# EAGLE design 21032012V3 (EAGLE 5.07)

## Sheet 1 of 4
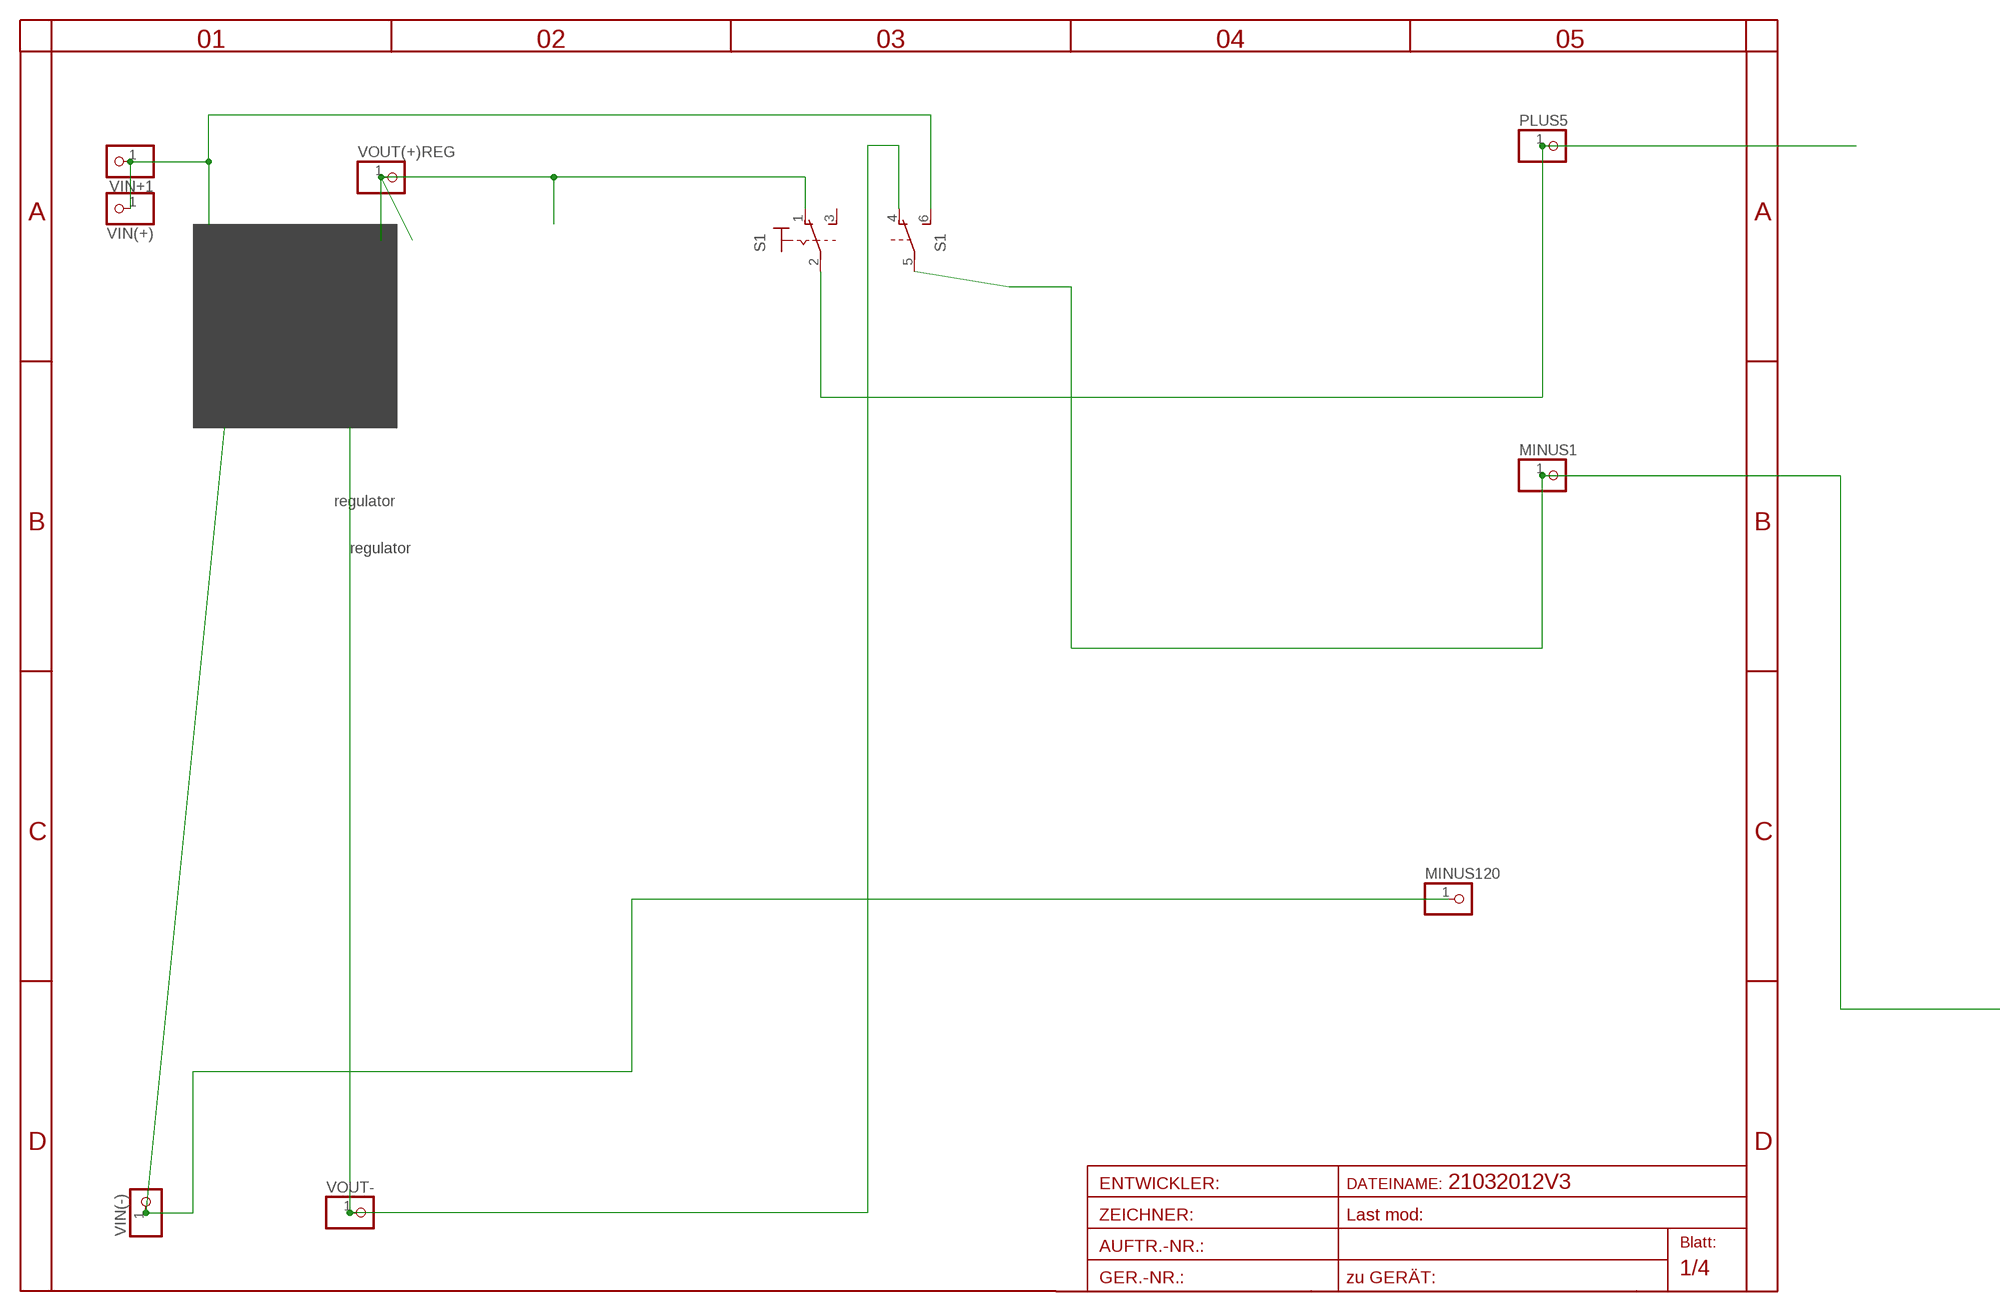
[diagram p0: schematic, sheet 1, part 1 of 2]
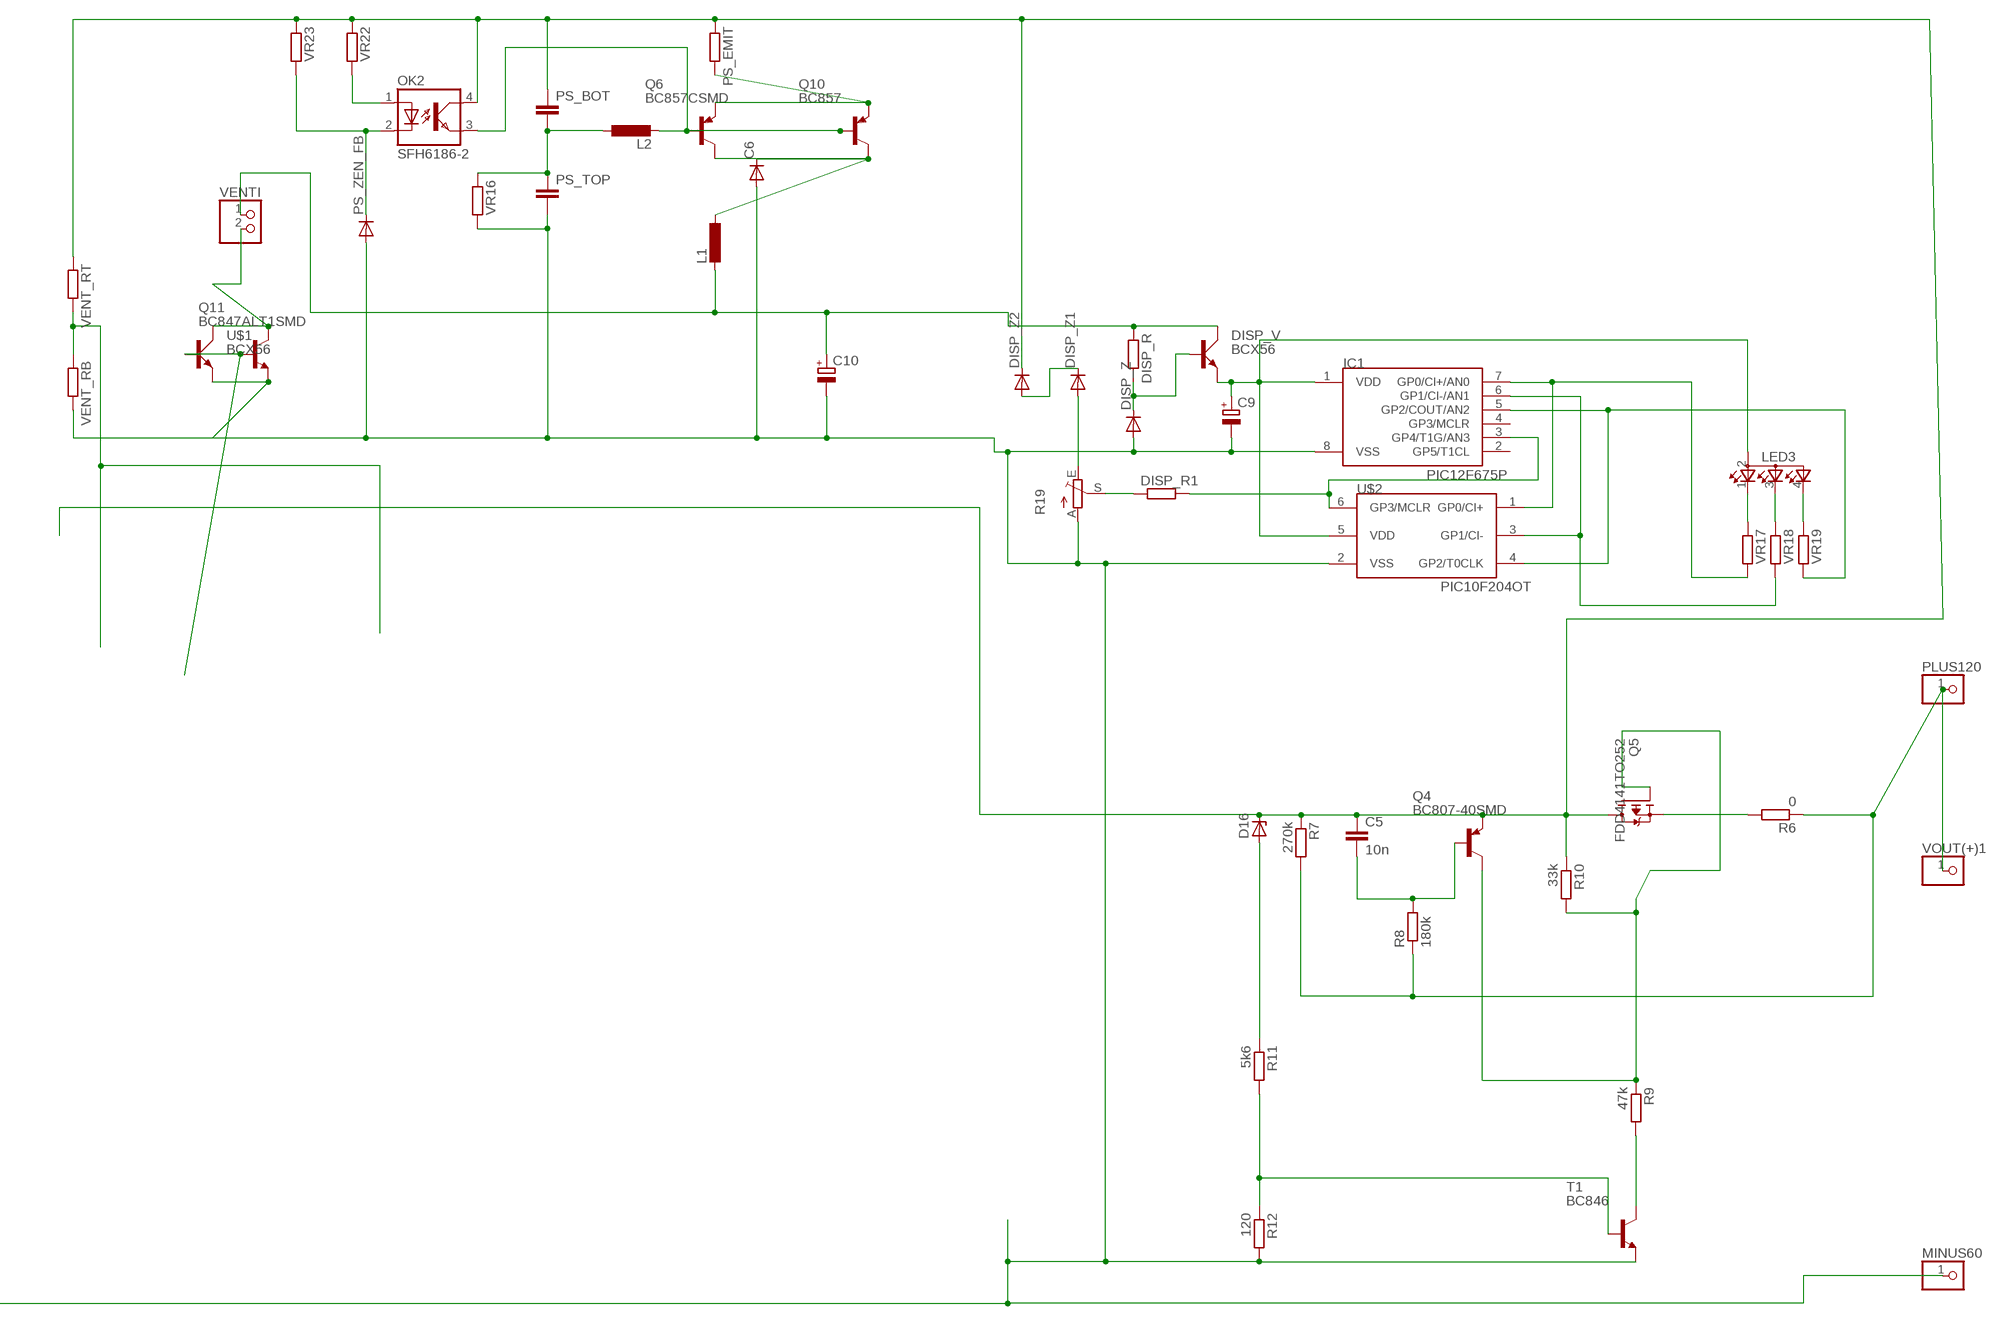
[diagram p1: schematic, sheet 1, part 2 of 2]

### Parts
C5  10n  C-EUC1206  [C1206]
C6  DIODE-SMB  [SMB]
C9  CPOL-EUE5-6  [E5-6]
C10  CPOL-EUE2.5-6  [E2,5-6]
D16  ZENER-DIODESOD80C  [SOD80C]
DISP_R  R-EU_R1206  [R1206]
DISP_R1  R-EU_R1206  [R1206]
DISP_V  BCX56  [SOT223]
DISP_Z  DIODE-MINIMELF  [MINIMELF]
DISP_Z1  DIODE-MINIMELF  [MINIMELF]
DISP_Z2  DIODE-MINIMELF  [MINIMELF]
IC1  PIC12F675P  [DIL8]
L1  L-EUL5650M  [L5650M]
L2  L-EUL5650M  [L5650M]
LED3  TOPLED-3  [P-LCC-4-3]
MINUS1  PINHD-1X14.5MM  [1X4MM5]
MINUS60  PINHD-1X14.5MM  [1X4MM5]
MINUS120  PINHD-1X14.5MM  [1X4MM5]
OK2  SFH6186-2  [SMD4]
PLUS5  PINHD-1X14.5MM  [1X4MM5]
PLUS120  PINHD-1X14.5MM  [1X4MM5]
PS_BOT  C-EUC1206  [C1206]
PS_EMIT  R-EU_R1210  [R1210]
PS_TOP  C-EUC1206  [C1206]
PS_ZEN_FB  DIODE-MINIMELF  [MINIMELF]
Q4  BC807-40SMD  [SOT23-BEC]
Q5  FDD4141TO252  [TO252]
Q6  BC857CSMD  [SOT23-BEC]
Q10  BC857  [SOT223]
Q11  BC847ALT1SMD  [SOT23]
R6  0  R-EU_0204/7  [0204/7]
R7  270k  R-EU_R1206  [R1206]
R8  180k  R-EU_R1206  [R1206]
R9  47k  R-EU_R1206  [R1206]
R10  33k  R-EU_R1206  [R1206]
R11  5k6  R-EU_R1206  [R1206]
R12  120  R-EU_R1206  [R1206]
R19  TRIM_EU-CA6V  [CA6V]
S1  320-938320NEW  [320NEW]
T1  BC846  [SOT23]
U$1  BCX56  [SOT223]
U$2  PIC10F204OT  [SOT23-6]
VENT_RB  R-EU_R1206  [R1206]
VENT_RT  R-EU_R1206  [R1206]
VENTI  PINHD-1X2  [1X02]
VIN(+)  PINHD-1X11MM6  [1X1MM8]
VIN(-)  PINHD-1X1  [1X01]
VIN+1  PINHD-1X1  [1X01]
VOUT(+)1  PINHD-1X11X0.4  [1X01]
VOUT(+)REG  PINHD-1X11X0.4  [1X01]
VOUT-  PINHD-1X11X0.4  [1X01]
VR16  R-EU_R1206  [R1206]
VR17  R-EU_R1206  [R1206]
VR18  R-EU_R1206  [R1206]
VR19  R-EU_R1206  [R1206]
VR22  R-EU_R1206  [R1206]
VR23  R-EU_R1206  [R1206]

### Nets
B-Q1: C5.2 Q4.B R8.2
BATT-: C6.A C9.- C10.- DISP_Z.A IC1.8(VSS) MINUS1.1 MINUS60.1 PS_TOP.2 PS_ZEN_FB.A Q11.2(E) R12.2 R19.A S1.5(B:P) T1.2(E) U$1.3(E) U$2.2(VSS) VENT_RB.2 VR16.2 ; also sheet 4
D: Q5.3(S) R6.2
GATE: Q4.C Q5.1(G) R9.1 R10.2
IN-: MINUS120.1 VIN(-).1 ; also sheet 3
N$18: R9.2 T1.3(C)
N$19: D16.A R11.1
N$21: R11.2 R12.1 T1.1(B)
N$22: C10.+ DISP_R.1 DISP_V.2(C) L1.2 VENTI.1
N$34: C9.+ DISP_V.3(E) IC1.1(VDD) LED3.2(A2) U$2.5(VDD)
N$35: IC1.7(GP0/CI+/AN0) U$2.1(GP0/CI+) VR17.2
N$36: IC1.6(GP1/CI-/AN1) U$2.3(GP1/CI-) VR18.2
N$37: IC1.5(GP2/COUT/AN2) U$2.4(GP2/T0CLK) VR19.2
N$38: PS_EMIT.2 Q6.E Q10.3(E)
N$39: L2.2 OK2.3(EMIT) Q6.B Q10.1(B)
N$40: C6.C L1.1 Q6.C Q10.2(C)
N$41: OK2.2(C) PS_ZEN_FB.C VR23.2
N$42: OK2.1(A) VR22.2
N$43: L2.1 PS_BOT.2 PS_TOP.1 VR16.1
N$44: VENT_RB.1 VENT_RT.2 ; also sheet 4
N$45: Q11.1(B) U$1.1(B) ; also sheet 4
N$46: DISP_R.2 DISP_V.1(B) DISP_Z.C
N$47: LED3.1(CRED) VR17.1
N$48: LED3.3(CBLUE) VR18.1
N$49: LED3.4(CGREEN) VR19.1
N$53: Q11.3(C) U$1.2(C) VENTI.2
N$69: DISP_Z1.A R19.E
N$75: DISP_R1.2 IC1.3(GP4/T1G/AN3) U$2.6(GP3/MCLR)
N$76: DISP_R1.1 R19.S
N$83: DISP_Z1.C DISP_Z2.A
PLUS5: C5.1 D16.C DISP_Z2.C OK2.4(COL) PLUS5.1 PS_BOT.1 PS_EMIT.1 Q4.E Q5.2(D) R7.1 R10.1 S1.2(1:P) VENT_RT.1 VR22.1 VR23.1 ; also sheet 4
V+OUT: PLUS120.1 R6.1 R7.2 R8.1 VOUT(+)1.1
V-: S1.4(B:O) VOUT-.1 ; also sheet 3
VIN+: S1.6(B:S) VIN(+).1 VIN+1.1 ; also sheet 3
VOUT+REG: S1.1(1:O) VOUT(+)REG.1 ; also sheet 2,3
Unconnected: IC1.2(GP5/T1CL) IC1.4(GP3/MCLR) S1.3(1:S)

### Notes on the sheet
- regulator
- regulator

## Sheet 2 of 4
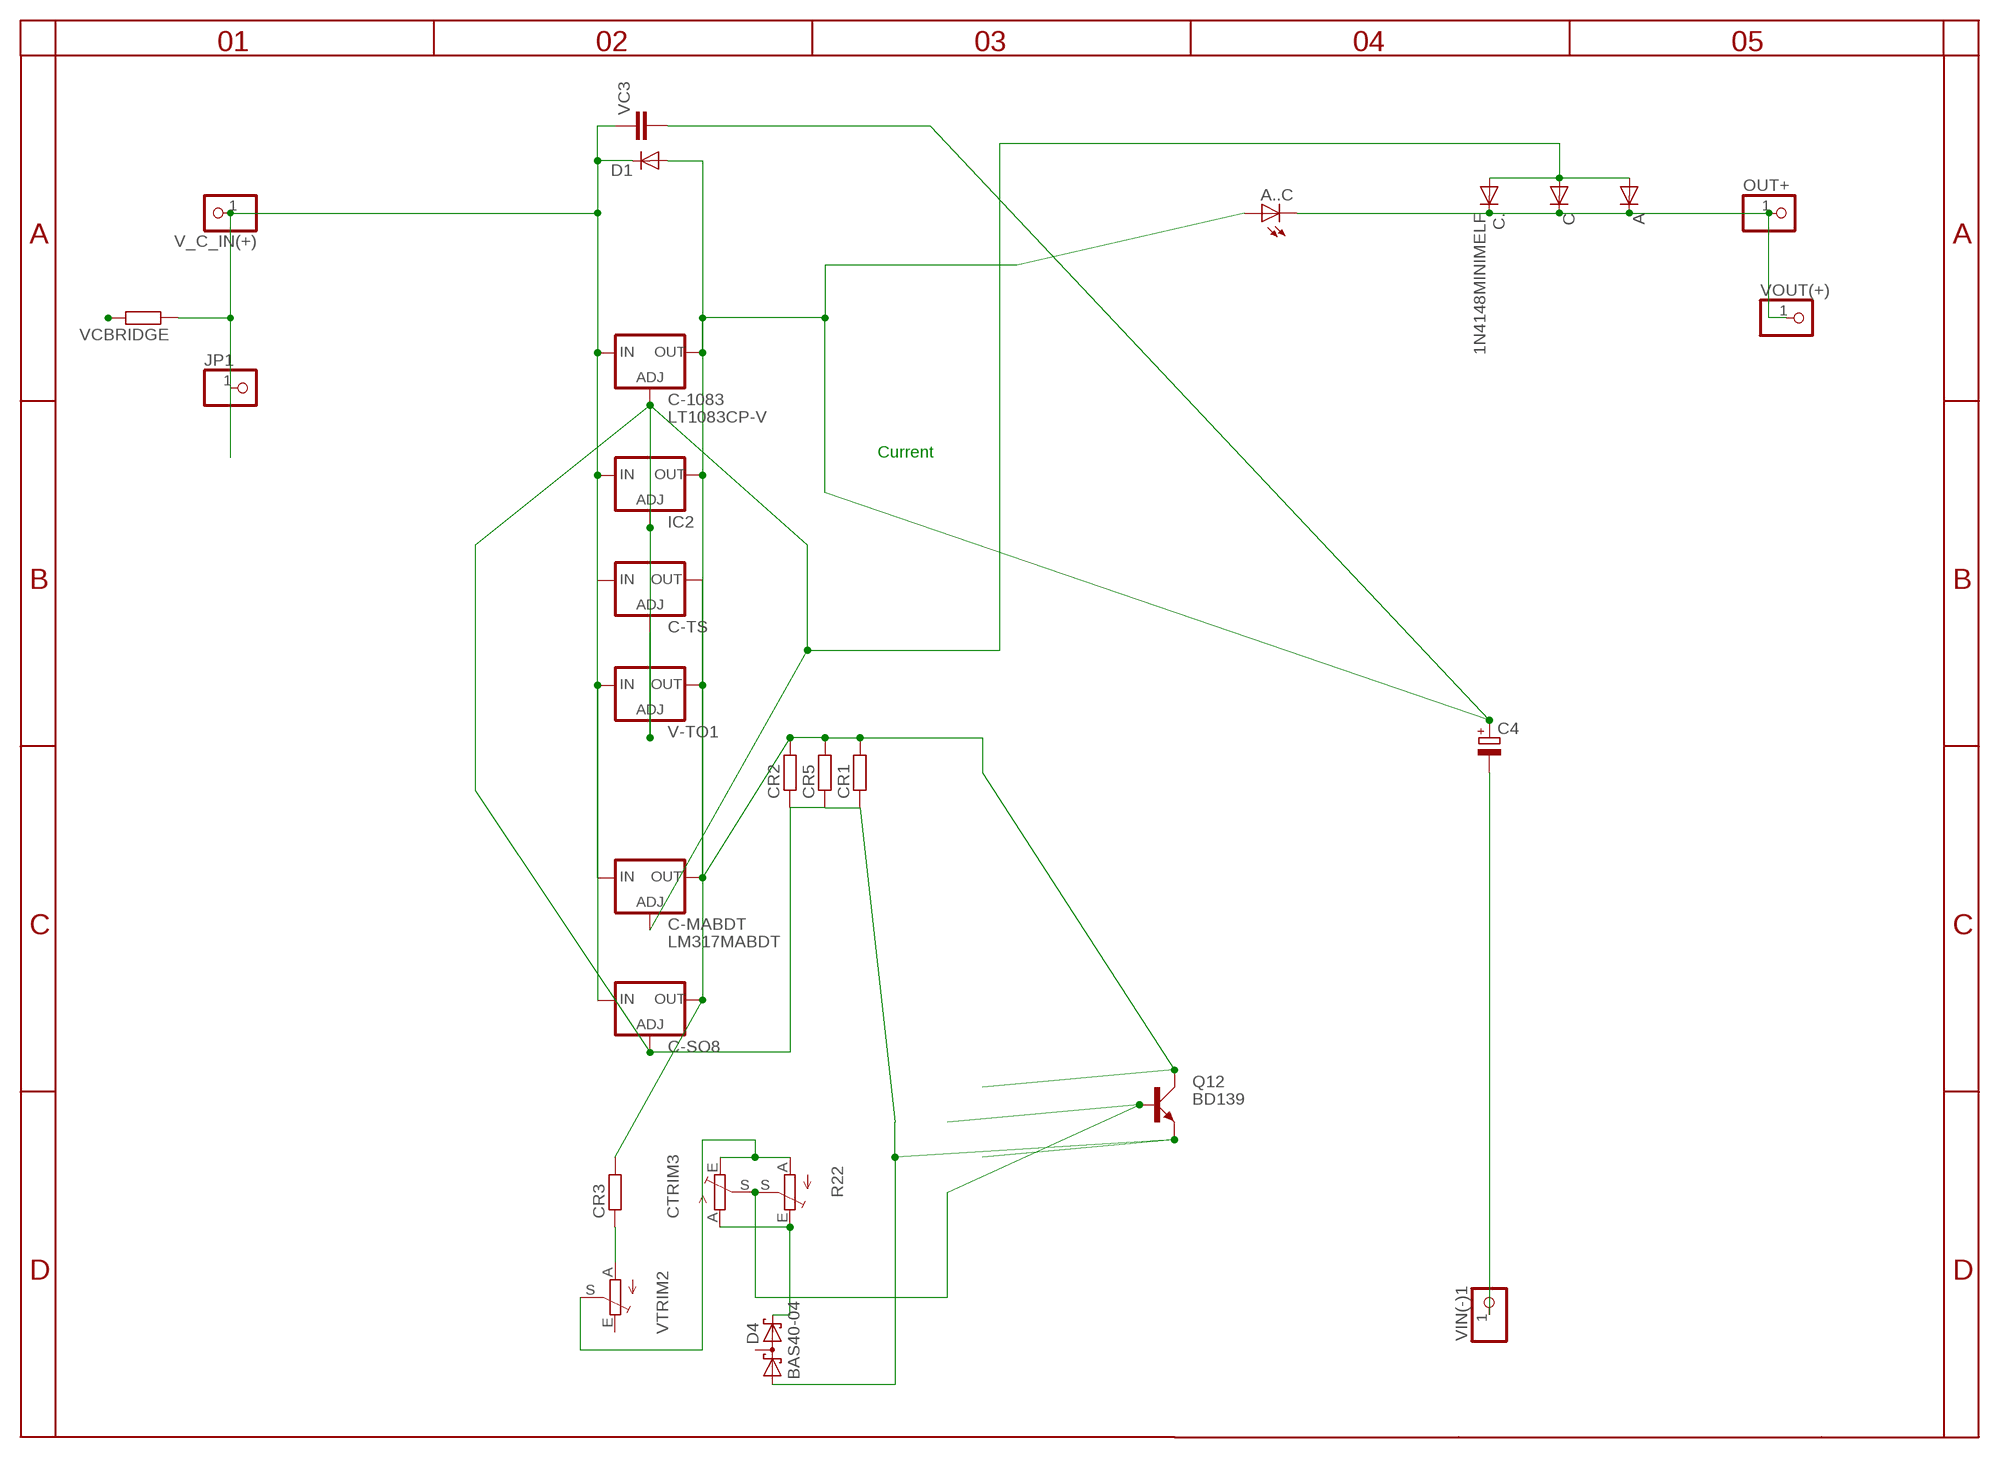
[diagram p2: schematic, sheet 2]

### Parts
A  DIODE-TO220V  [TO220ACS]
A..C  LED3MM  [LED3MM]
C  DIODE-SMB  [SMB]
C4  CPOL-EUE5-6  [E5-6]
C-1083  LT1083CP-V  [TO247S]
C-MABDT  LM317MABDT  [DPACK]
C-SO8  LM317LM-OUTPIN7  [SO08]
C-TS  LM317TS  [317TS]
C.  1N4148MINIMELF  [MINIMELF]
CR1  R-EU_R5025  [R5025]
CR2  R-EU_R1206  [R1206]
CR3  R-EU_0204/5  [0204/5]
CR5  R-EU_R1210  [R1210]
CTRIM3  TRIM_EU-EVND_H  [EVND8AA]
D1  DIODE-MINIMELF  [MINIMELF]
D4  BAS40-04  [SOT23]
IC2  LM317LZS  [TO92S]
JP1  PINHD-1X11MM6  [1X1MM8]
OUT+  PINHD-1X1  [1X01]
Q12  BD139  [TO126AV]
R22  TRIM_EU-RAND160  [RANDL]
V-TO1  LM317-TO3  [TO3-K02]
V_C_IN(+)  PINHD-1X11X0.4  [1X01]
VC3  C-EU050-025X075  [C050-025X075]
VCBRIDGE  R-EU_R0402  [R0402]
VIN(-)1  PINHD-1X1  [1X01]
VOUT(+)  PINHD-1X11X0.4  [1X01]
VTRIM2  TRIM_EU-EVND_H  [EVND8AA]

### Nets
ADJUST: A.A C-1083.1(ADJ) C-MABDT.1(ADJ) C-SO8.4(ADJ) C-TS.1(ADJ) C..A C.A CR1.1 CR2.1 CR5.1 D4.1(A1) IC2.1(ADJ) Q12.E V-TO1.2(ADJ)
B1: CTRIM3.S Q12.B R22.S
INPUT+: C-1083.3(IN) C-MABDT.3(IN) C-SO8.1(IN) C-TS.3(IN) D1.C IC2.3(IN) JP1.1 V-TO1.1(IN) V_C_IN(+).1 VC3.1 VCBRIDGE.1
MINUS: CTRIM3.A D4.2(C2) R22.E
N$5: CTRIM3.E R22.A VTRIM2.S
N$6: CR3.1 VTRIM2.A
N$9: C4.- VIN(-)1.1
OUT1: A..C.A C4.+ C-1083.2(OUT) C-MABDT.4(OUT) C-SO8.7(OUT) C-TS.2(OUT) CR1.2 CR2.2 CR3.2 CR5.2 D1.A IC2.2(OUT) Q12.C V-TO1.3(OUT) VC3.2
OUT+: A..C.K(C) A.C C..C C.C OUT+.1 VOUT(+).1
VOUT+REG: VCBRIDGE.2 ; also sheet 1,3
Unconnected: D4.3(C1A2) VTRIM2.E

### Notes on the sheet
- Current

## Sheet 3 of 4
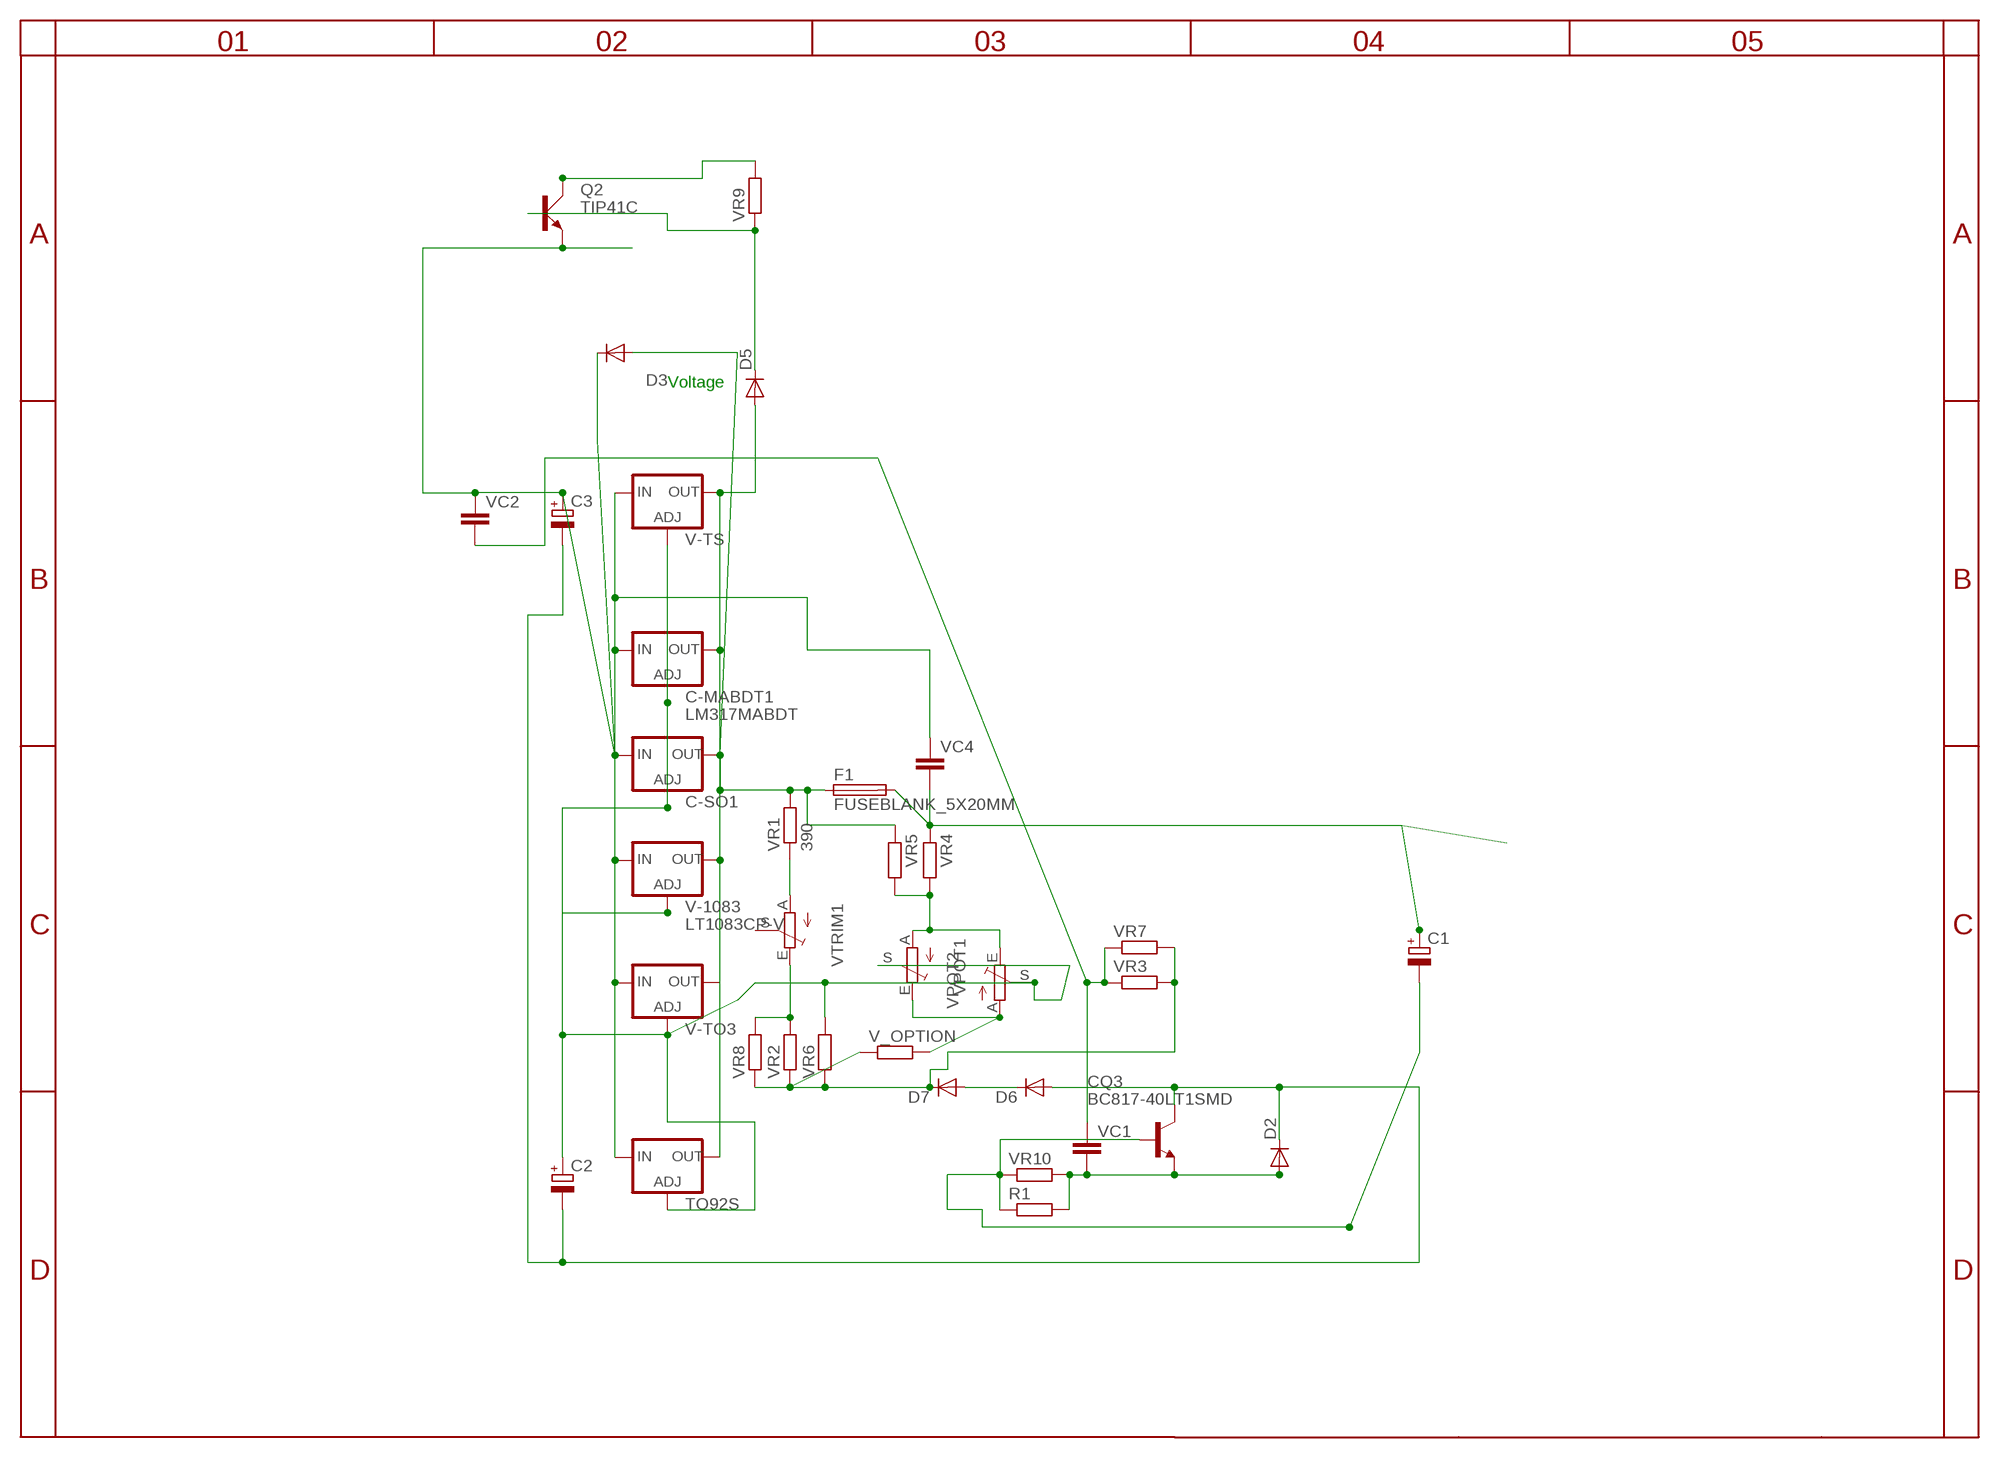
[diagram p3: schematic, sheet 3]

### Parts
C1  CPOL-EUE5-8.5  [E5-8,5]
C2  CPOL-EUE2.5-6  [E2,5-6]
C3  CPOL-EUE2.5-6  [E2,5-6]
C-MABDT1  LM317MABDT  [DPACK]
C-SO1  LM317LM-OUTPIN7  [SO08]
CQ3  BC817-40LT1SMD  [SOT23-BEC]
D2  DIODE-MINIMELF  [MINIMELF]
D3  DIODE-MINIMELF  [MINIMELF]
D5  DIODE-MINIMELF  [MINIMELF]
D6  DIODE-MINIMELF  [MINIMELF]
D7  DIODE-MINIMELF  [MINIMELF]
F1  FUSEBLANK_5X20MM  [FUSE_HOLDER_5X20MM]
Q2  TIP41C  [TO220AV]
R1  R-EU_R2010  [R2010]
TO92S  LM317LZS  [TO92S]
V-1083  LT1083CP-V  [TO247S]
V-TO3  LM317-TO3  [TO3-K02]
V-TS  LM317TS  [317TS]
V_OPTION  R-EU_0204/2V  [0204V]
VC1  C-EU050-025X075  [C050-025X075]
VC2  C-EU050-025X075  [C050-025X075]
VC4  C-EUC1206  [C1206]
VPOT1  TRIM_EU-RAND160  [RANDL]
VPOT2  TRIM_EU-S64W  [S64W]
VR1  390  R-EU_0207/15  [0207/15]
VR2  R-EU_0204/2V  [0204V]
VR3  R-EU_0204/5  [0204/5]
VR4  R-EU_R1206  [R1206]
VR5  R-EU_R1206  [R1206]
VR6  R-EU_R1206  [R1206]
VR7  R-EU_R1206  [R1206]
VR8  R-EU_R1206  [R1206]
VR9  R-EU_R1206  [R1206]
VR10  R-EU_0617/17  [0617/17]
VTRIM1  TRIM_EU-EVND_H  [EVND8AA]

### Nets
ADJ2: C2.+ C-MABDT1.1(ADJ) C-SO1.4(ADJ) TO92S.1(ADJ) V-1083.1(ADJ) V-TO3.2(ADJ) V-TS.1(ADJ) VPOT1.S VPOT2.S VR6.2
IN+1: C3.+ C-MABDT1.3(IN) C-SO1.1(IN) D3.C Q2.E TO92S.3(IN) V-1083.3(IN) V-TO3.1(IN) V-TS.3(IN) VC2.1 VC4.1
IN-: CQ3.E D2.A R1.2 VC1.2 VR10.2 ; also sheet 1
N$1: V_OPTION.2 VPOT1.E VPOT2.A
N$2: VPOT1.A VPOT2.E VR4.2 VR5.2
N$3: VR2.2 VR8.2 VTRIM1.E
N$4: VR1.1 VTRIM1.A
N$7: VC1.1 VC2.2 VR3.1 VR7.1
N$10: D5.C Q2.B VR9.1
N$12: D7.C V_OPTION.1 VR2.1 VR3.2 VR6.1 VR7.2 VR8.1
N$13: D6.C D7.A
OUT2: C-MABDT1.4(OUT) C-SO1.7(OUT) D3.A D5.A F1.1 TO92S.2(OUT) V-1083.2(OUT) V-TO3.3(OUT) V-TS.2(OUT) VR1.2 VR5.1
V-: C1.- CQ3.B R1.1 VR10.1 ; also sheet 1
VIN+: Q2.C VR9.2 ; also sheet 1
VIRT-: C2.- C3.- CQ3.C D2.C D6.A
VOUT+REG: C1.+ F1.2 VC4.2 VR4.1 ; also sheet 1,2
Unconnected: VTRIM1.S

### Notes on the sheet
- Voltage

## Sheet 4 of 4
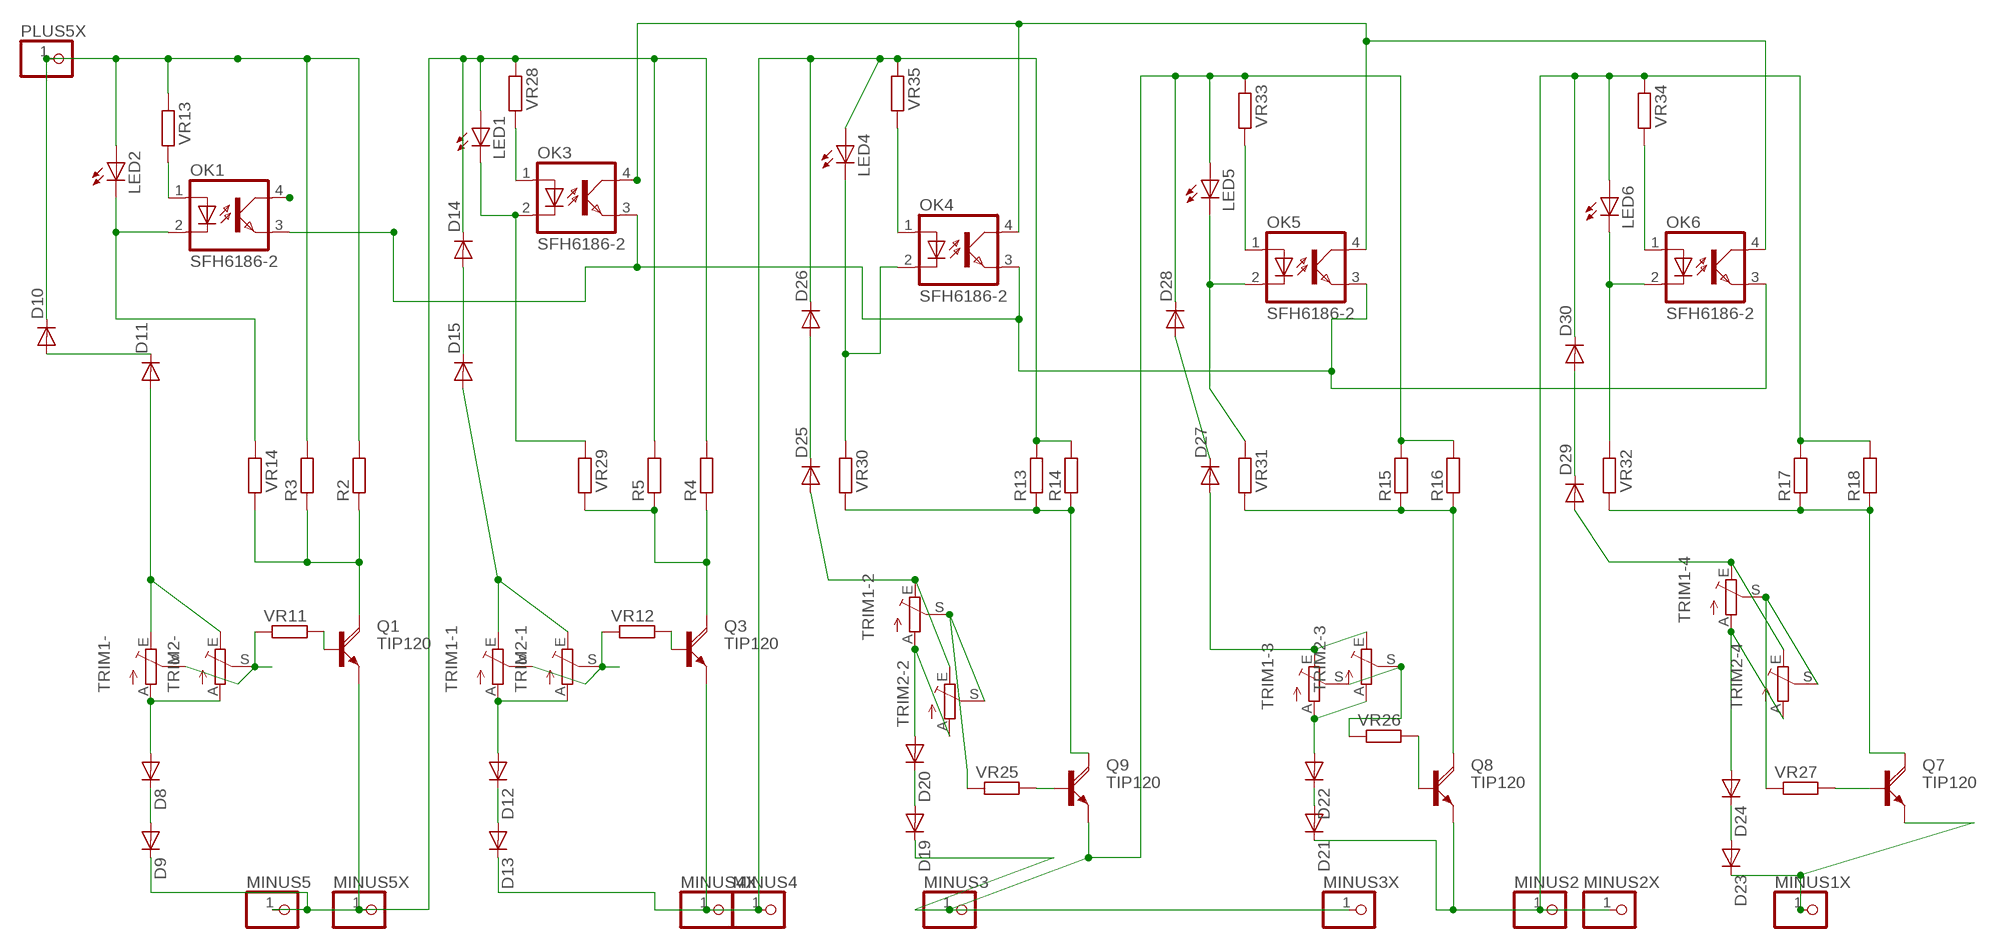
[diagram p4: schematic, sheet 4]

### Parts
D8  DIODE-MINIMELF  [MINIMELF]
D9  DIODE-MINIMELF  [MINIMELF]
D10  DIODE-MINIMELF  [MINIMELF]
D11  DIODE-MINIMELF  [MINIMELF]
D12  DIODE-MINIMELF  [MINIMELF]
D13  DIODE-MINIMELF  [MINIMELF]
D14  DIODE-MINIMELF  [MINIMELF]
D15  DIODE-MINIMELF  [MINIMELF]
D19  DIODE-MINIMELF  [MINIMELF]
D20  DIODE-MINIMELF  [MINIMELF]
D21  DIODE-MINIMELF  [MINIMELF]
D22  DIODE-MINIMELF  [MINIMELF]
D23  DIODE-MINIMELF  [MINIMELF]
D24  DIODE-MINIMELF  [MINIMELF]
D25  DIODE-MINIMELF  [MINIMELF]
D26  DIODE-MINIMELF  [MINIMELF]
D27  DIODE-MINIMELF  [MINIMELF]
D28  DIODE-MINIMELF  [MINIMELF]
D29  DIODE-MINIMELF  [MINIMELF]
D30  DIODE-MINIMELF  [MINIMELF]
LED1  LEDCHIPLED_1206  [CHIPLED_1206]
LED2  LEDCHIPLED_1206  [CHIPLED_1206]
LED4  LEDCHIPLED_1206  [CHIPLED_1206]
LED5  LEDCHIPLED_1206  [CHIPLED_1206]
LED6  LEDCHIPLED_1206  [CHIPLED_1206]
MINUS1X  PINHD-1X11X0.4  [1X01]
MINUS2  PINHD-1X14.5MM  [1X4MM5]
MINUS2X  PINHD-1X11X0.4  [1X01]
MINUS3  PINHD-1X14.5MM  [1X4MM5]
MINUS3X  PINHD-1X11X0.4  [1X01]
MINUS4  PINHD-1X14.5MM  [1X4MM5]
MINUS4X  PINHD-1X11X0.4  [1X01]
MINUS5  PINHD-1X14.5MM  [1X4MM5]
MINUS5X  PINHD-1X11X0.4  [1X01]
OK1  SFH6186-2  [SMD4]
OK3  SFH6186-2  [SMD4]
OK4  SFH6186-2  [SMD4]
OK5  SFH6186-2  [SMD4]
OK6  SFH6186-2  [SMD4]
PLUS5X  PINHD-1X11X0.4  [1X01]
Q1  TIP120  [D-PAK_TO252AA]
Q3  TIP120  [D-PAK_TO252AA]
Q7  TIP120  [D-PAK_TO252AA]
Q8  TIP120  [D-PAK_TO252AA]
Q9  TIP120  [D-PAK_TO252AA]
R2  R-EU_CERAM55  [CERAM55]
R3  R-EU_CERAM55  [CERAM55]
R4  R-EU_CERAM55  [CERAM55]
R5  R-EU_CERAM55  [CERAM55]
R13  R-EU_CERAM55  [CERAM55]
R14  R-EU_CERAM55  [CERAM55]
R15  R-EU_CERAM55  [CERAM55]
R16  R-EU_CERAM55  [CERAM55]
R17  R-EU_CERAM55  [CERAM55]
R18  R-EU_CERAM55  [CERAM55]
TRIM1-  TRIM_EU-EVND_H  [EVND8AA]
TRIM1-1  TRIM_EU-EVND_H  [EVND8AA]
TRIM1-2  TRIM_EU-EVND_H  [EVND8AA]
TRIM1-3  TRIM_EU-EVND_H  [EVND8AA]
TRIM1-4  TRIM_EU-EVND_H  [EVND8AA]
TRIM2-  TRIM_EU-S64W  [S64W]
TRIM2-1  TRIM_EU-S64W  [S64W]
TRIM2-2  TRIM_EU-S64W  [S64W]
TRIM2-3  TRIM_EU-S64W  [S64W]
TRIM2-4  TRIM_EU-S64W  [S64W]
VR11  R-EU_R1206  [R1206]
VR12  R-EU_R1206  [R1206]
VR13  R-EU_R1206  [R1206]
VR14  R-EU_R1206  [R1206]
VR25  R-EU_R1206  [R1206]
VR26  R-EU_R1206  [R1206]
VR27  R-EU_R1206  [R1206]
VR28  R-EU_R1206  [R1206]
VR29  R-EU_R1206  [R1206]
VR30  R-EU_R1206  [R1206]
VR31  R-EU_R1206  [R1206]
VR32  R-EU_R1206  [R1206]
VR33  R-EU_R1206  [R1206]
VR34  R-EU_R1206  [R1206]
VR35  R-EU_R1206  [R1206]

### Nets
B: TRIM1-.S TRIM2-.S VR11.1
B2: TRIM1-1.S TRIM2-1.S VR12.1
BATT-: D23.C MINUS1X.1 Q7.3(E) ; also sheet 1
N$8: D13.C D26.C LED4.A MINUS4.1 MINUS4X.1 Q3.3(E) R13.2 R14.2 VR35.1
N$11: LED2.C OK1.2(C) VR14.1
N$14: D11.A TRIM1-.E TRIM2-.E
N$15: D8.A TRIM1-.A TRIM2-.A
N$16: OK3.1(A) VR28.2
N$17: D10.A D11.C
N$20: Q1.4(C) R2.1 R3.1 VR14.2
N$23: OK1.1(A) VR13.2
N$24: D8.C D9.A
N$25: Q1.1(B) VR11.2
N$26: D15.A TRIM1-1.E TRIM2-1.E
N$27: D12.A TRIM1-1.A TRIM2-1.A
N$28: D9.C D14.C LED1.A MINUS5.1 MINUS5X.1 Q1.3(E) R4.2 R5.2 VR28.1
N$29: D14.A D15.C
N$30: Q3.4(C) R4.1 R5.1 VR29.2
N$31: LED1.C OK3.2(C) VR29.1
N$32: D12.C D13.A
N$33: Q3.1(B) VR12.2
N$44: OK1.4(COL) OK3.4(COL) OK4.4(COL) OK5.4(COL) OK6.4(COL) ; also sheet 1
N$45: OK1.3(EMIT) OK3.3(EMIT) OK4.3(EMIT) OK5.3(EMIT) OK6.3(EMIT) ; also sheet 1
N$50: Q9.1(B) VR25.2
N$51: Q8.1(B) VR26.2
N$52: Q7.1(B) VR27.2
N$54: D20.A TRIM1-2.A TRIM2-2.A
N$55: D25.A TRIM1-2.E TRIM2-2.E
N$56: Q9.4(C) R13.1 R14.1 VR30.2
N$57: TRIM1-2.S TRIM2-2.S VR25.1
N$58: Q8.4(C) R15.1 R16.1 VR31.2
N$59: D19.C D28.C LED5.A MINUS3.1 MINUS3X.1 Q9.3(E) R15.2 R16.2 VR33.1
N$60: D21.C D30.C LED6.A MINUS2.1 MINUS2X.1 Q8.3(E) R17.2 R18.2 VR34.1
N$61: Q7.4(C) R17.1 R18.1 VR32.2
N$62: D22.A TRIM1-3.A TRIM2-3.A
N$63: D27.A TRIM1-3.E TRIM2-3.E
N$64: TRIM1-3.S TRIM2-3.S VR26.1
N$65: D24.A TRIM1-4.A TRIM2-4.A
N$66: D29.A TRIM1-4.E TRIM2-4.E
N$67: TRIM1-4.S TRIM2-4.S VR27.1
N$68: D23.A D24.C
N$70: D21.A D22.C
N$71: D25.C D26.A
N$72: D19.A D20.C
N$73: D27.C D28.A
N$74: D29.C D30.A
N$77: LED4.C OK4.2(C) VR30.1
N$78: LED5.C OK5.2(C) VR31.1
N$79: LED6.C OK6.2(C) VR32.1
N$80: OK4.1(A) VR35.2
N$81: OK5.1(A) VR33.2
N$82: OK6.1(A) VR34.2
PLUS5: D10.C LED2.A PLUS5X.1 R2.2 R3.2 VR13.1 ; also sheet 1

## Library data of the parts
A C C6 D1-D3 D5-D15 D19-D30 DISP_Z DISP_Z1 DISP_Z2 PS_ZEN_FB = diode:DIODE-: DIODE
A..C LED1 LED2 LED4-LED6 = led:LED: LED
C1-C4 C9 C10 = rcl:CPOL-EU: POLARIZED CAPACITOR, European symbol
C5 = rcl-2:C-EU: CAPACITOR, European symbol
C-1083 V-1083 = linear-technology-2:LT1083*: 7.5A Low Dropout Positive Adjustable Regulators
C-MABDT C-MABDT1 = v-reg:LM317?*: 500 mA Adjustable Output Positive Voltage Regulator Source: http://www.onsemi.co.jp .. LM317M-D.PDF
C-SO1 C-SO8 IC2 TO92S = v-reg-3:LM317L: Adjustable Voltage Regulator, 1.2V to 37V, 100mA
C-TS V-TS = v-reg:LM317TS: VOLTAGE REGULATOR
C. = diode-1:1N4148: DIODE
CQ3 = transistor-npn:BC817*: NPN Transistor
CR1-CR3 CR5 DISP_R DISP_R1 PS_EMIT R6-R12 V_OPTION VCBRIDGE VENT_RB VENT_RT VR1-VR14 VR16-VR19 VR22 VR23 VR25-VR35 = rcl-2:R-EU_: RESISTOR, European symbol
CTRIM3 R22 TRIM1- TRIM1-1-TRIM1-4 TRIM2- TRIM2-1-TRIM2-4 VPOT1 VPOT2 VTRIM1 VTRIM2 = pot:TRIM_EU-: POTENTIOMETER
D4 = diode:BAS40-04: Silicon Schottky Diodes General-purpose diode for high-speed switching
D16 = diode-1:ZENER-DIODE: Z-Diode
DISP_V U$1 = transistor-power:BCX56
F1 = fuse:FUSE: Fuse
IC1 = microchip-5:PIC12F6*: uPC nW 1k Program Flash memory 2x Timer Comparator 10b A/D converter/ 4xIN
JP1 MINUS1 MINUS1X MINUS2 MINUS2X MINUS3 MINUS3X MINUS4 MINUS4X MINUS5 MINUS5X MINUS60 MINUS120 PLUS5 PLUS5X PLUS120 V_C_IN(+) VIN(+) VOUT(+) VOUT(+)1 VOUT(+)REG VOUT- = pinhead:PINHD-1X1: PIN HEADER
L1 L2 = rcl:L-EU: INDUCTOR, European symbol
LED3 = led:TOPLED-3: OSRAM - Hyper Multi TOPLED® (RGB) LB E673, LV E673, LT E673 - Power TOPLED® Enhanced optical Power LED (HOP2000) LS E67B, LA E67B, LO E67B, LY E67B - Hyper Multi TOPLED® Enhanced optical Power LED (HOP2000 / ATON®) LATB T66B - Hyper Multi TOPLED® Hyper-Bright LED LATB T686 Source: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
OK1-OK6 = optocoupler:SFH618?*: Optocoupler, Phototransistor Output, Low Input Current Source: http://www.vishay.com/docs/83673/sfh618.pdf
OUT+ VIN(-) VIN(-)1 VIN+1 = pinhead(2):PINHD-1X1: PIN HEADER
PS_BOT PS_TOP VC1-VC4 = rcl:C-EU: CAPACITOR, European symbol
Q1 Q3 Q7-Q9 = transistor-power:TIP120: NPN DARLINGTON TRANSISTOR
Q2 = transistor-power:TIP41C: NPN TRANSISTOR
Q4 = transistor-pnp:BC807*: PNP Transistror
Q5 = transistor-fet:FDD4141: P-Channel PowerTrench® MOSFET Source: FDD4141.pdf
Q6 Q10 = transistor-pnp:BC857*: PNP Transistror
Q11 = transistor-npn:BC847*: NPN Transistor
Q12 = transistor-power:BD139: NPN TRANSISTOR
R1-R5 R13-R18 = rcl:R-EU_: RESISTOR, European symbol
R19 = pot-7:TRIM_EU-: POTENTIOMETER
S1 = switch:320-938: TOGGLE SWITCH distributor RS Components
T1 = transistor:BC846: NPN TRANSISTOR
U$2 = microchip-5:PIC10F2*: uPC nW 0,25/0,5k Program Flash memory Comparator
V-TO1 V-TO3 = v-reg:LM317-TO3: VOLTAGE REGULATOR
VENTI = pinhead(2):PINHD-1X2: PIN HEADER

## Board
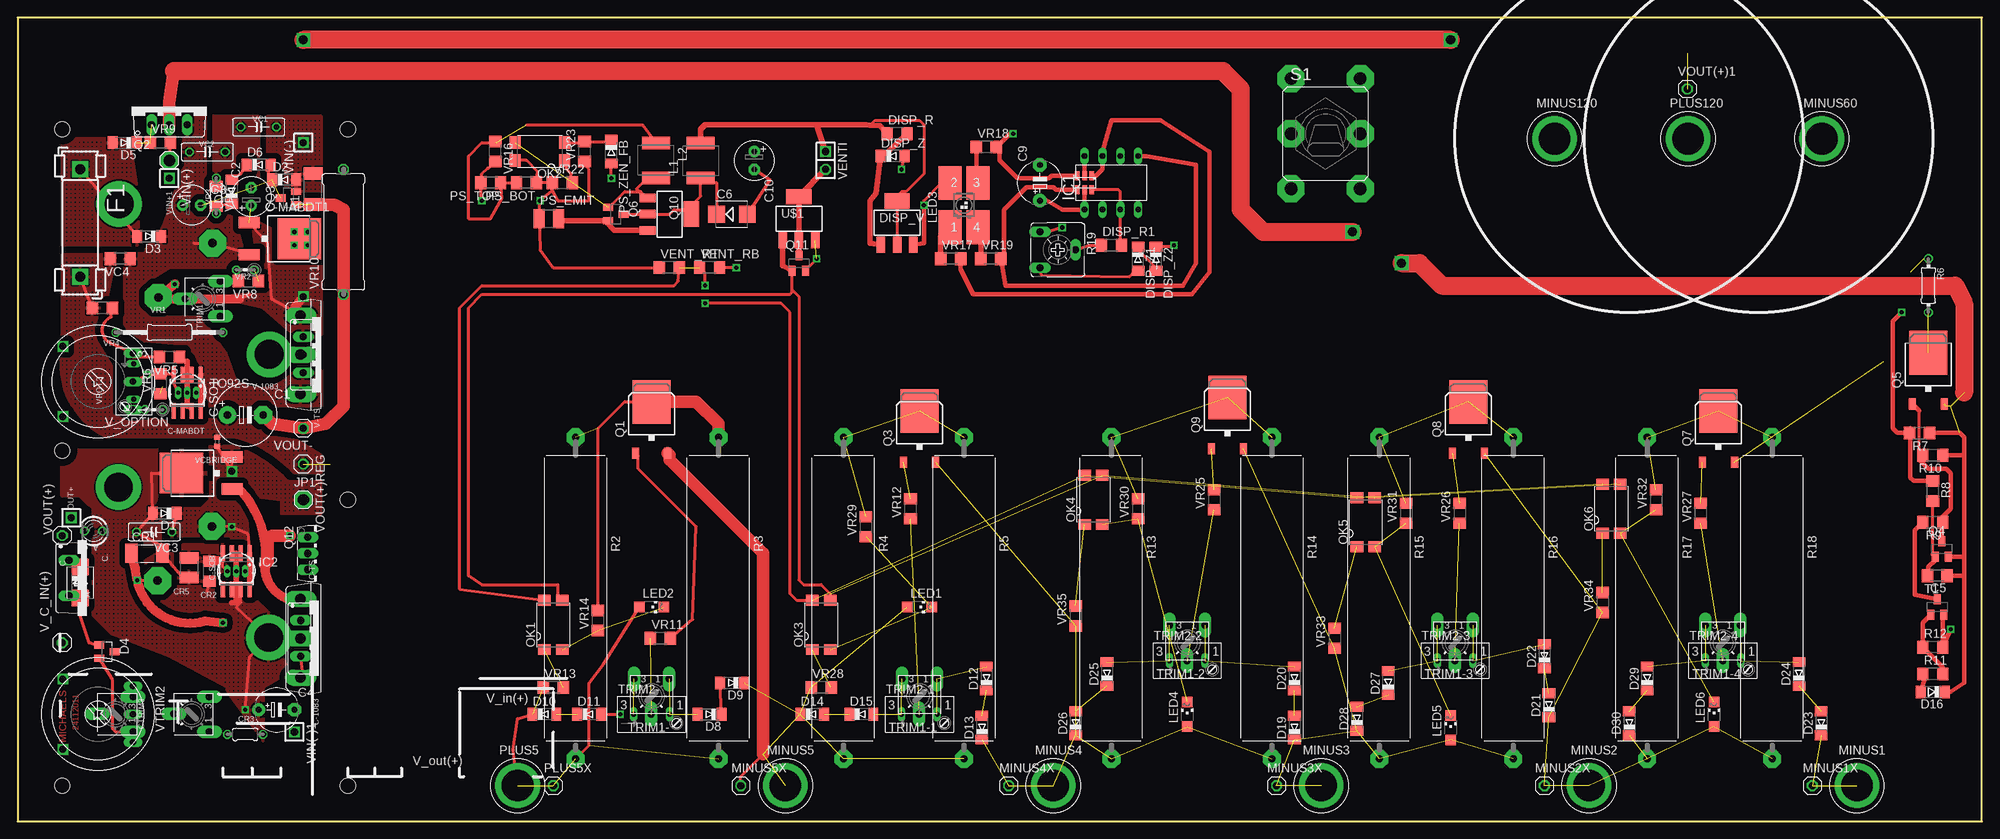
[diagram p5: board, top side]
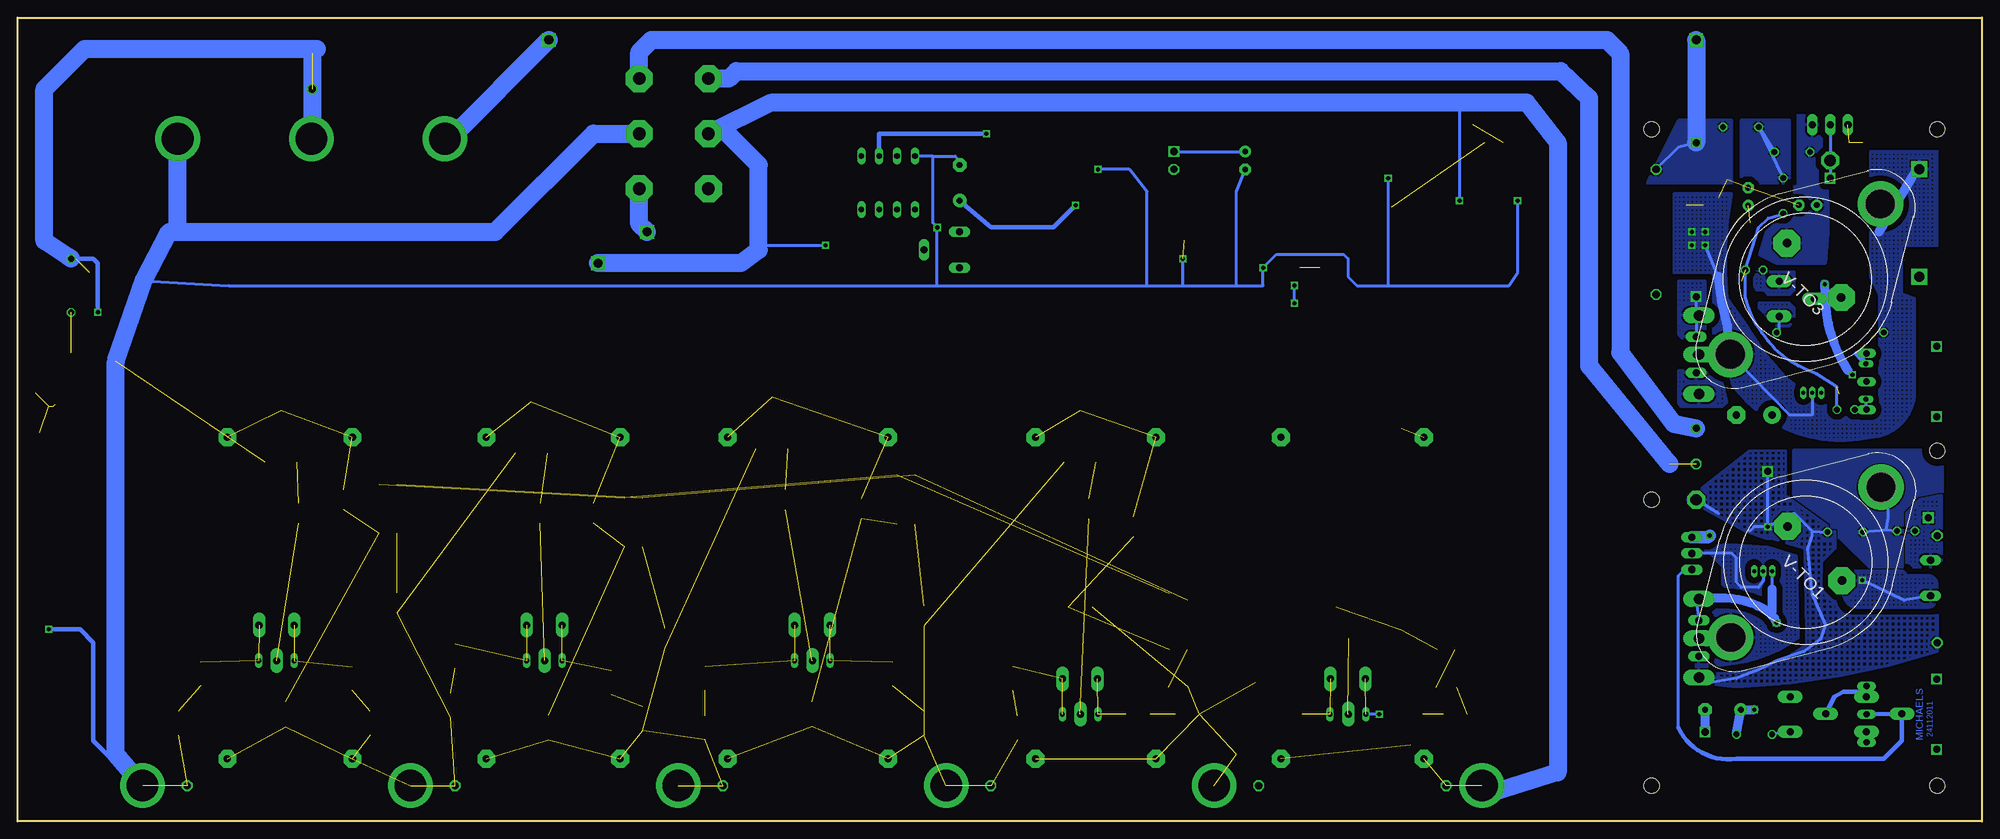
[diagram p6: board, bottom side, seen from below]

Size 279.4 x 114.3 mm. Coordinates in mm from the lower left corner, seen from the top.
Outline: 279.4,0 279.4,114.3 0,114.3 0,0 279.4,0
Copper layers (1*16): Top 0.035mm / dielectric 1.5mm / Bottom 0.035mm
Design rules "default *": minimum track width 10mil, minimum drill 24mil, track to track 8mil, track to pad 8mil, pad to pad 8mil, via to via 8mil, smd to smd 8mil, copper to edge 40mil, drill to drill 8mil, minimum pad ring 1mil, minimum via ring 8mil, stop-mask expansion 4mil, vias tented up to drill 0mil, thermal gap 10mil
Holes 2.2 mm at 6.35,5.08 46.99,45.72 6.35,52.7 46.99,5.08 6.35,98.42 46.99,98.42

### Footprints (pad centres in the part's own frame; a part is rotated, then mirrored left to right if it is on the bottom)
TO220ACS = drill 1.016 long: A 2.54,-2.54; C -2.54,-2.54
LED3MM = drill 0.813 octagon: A -1.27,0; K 1.27,0
SMB = smd 2.4 x 2.4: A 2.2,0; C -2.2,0
E5-8,5 = drill 1.016 pad 2.54 round: + -2.54,0 | drill 1.016 pad 2.54 octagon: - 2.54,0
E2,5-6 = drill 0.813 pad 1.6 round: + -1.27,0 | drill 0.813 pad 1.6 octagon: - 1.27,0
E5-6 = drill 0.813 pad 1.905 round: + -2.54,0 | drill 0.813 pad 1.905 octagon: - 2.54,0
C1206 = smd 1.6 x 1.8: 1 -1.4,0; 2 1.4,0
TO247S = drill 1.499 long: 1 -5.588,-2.921; 2 0,-2.921; 3 5.588,-2.921
DPACK = smd 1.6 x 3: 1 -2.28,-4.8; 3 2.28,-4.8 | smd 5.8 x 6.2: 4 0,2.38
SO08 = smd 0.6 x 2.2: 1 -1.905,-2.6; 2 -0.635,-2.6; 3 0.635,-2.6; 4 1.905,-2.6; 5 1.905,2.6; 6 0.635,2.6; 7 -0.635,2.6; 8 -1.905,2.6
317TS = drill 1.016 long: 1 -2.54,-2.54; 2 0,-2.54; 3 2.54,-2.54
MINIMELF = smd 1.4 x 1.8: A 1.7,0; C -1.7,0
SOT23-BEC = smd 1 x 1.4: B -0.95,-1.1; C 0,1.1; E 0.95,-1.1
R5025 = smd 1.8 x 2.7: 1 -2.2,0; 2 2.2,0
R1206 = smd 1.6 x 1.803: 1 -1.422,0; 2 1.422,0
0204/5 = drill 0.813 octagon: 1 -2.54,0; 2 2.54,0
R1210 = smd 1.6 x 2.7: 1 -1.4,0; 2 1.4,0
EVND8AA = drill 1 pad 1.778 long: A -2.5,-2.5; E 2.5,-2.5; S 0.04,2.54
SOT23 = smd 1 x 1.4: 1 -0.95,-1.1; 2 0.95,-1.1; 3 0,1.1
SOD80C = smd 1.4 x 1.8: A 1.7,0; C -1.7,0
SOT223 = smd 1.219 x 2.235: 1 -2.311,-3.099; 2 0,-3.099; 3 2.311,-3.099 | smd 3.6 x 2.2: 4 0,3.099
FUSE_HOLDER_5X20MM = drill 1.422 pad 2.286 square: 1 0,0; 2 15.24,0
DIL8 = drill 0.813 long: 1 -3.81,-3.81; 2 -1.27,-3.81; 3 1.27,-3.81; 4 3.81,-3.81; 5 3.81,3.81; 6 1.27,3.81; 7 -1.27,3.81; 8 -3.81,3.81
TO92S = drill 0.6 pad 0.813 long: 1 -1.27,0; 2 0,0; 3 1.27,0
1X1MM8 = drill 1.6 pad 2.54 octagon: 1 0,0
L5650M = smd 1.8 x 4: 1 -2.5,0; 2 2.5,0
CHIPLED_1206 = smd 1.5 x 1.5: A 0,-1.75; C 0,1.75
P-LCC-4-3 = smd 3.3 x 4.8: 1 -2,-3.15; 2 -2,3.15; 3 2,3.15; 4 2,-3.15
1X4MM5 = drill 4.5 pad 6.35 round: 1 0,0
1X01 = drill 1.016 octagon: 1 0,0
SMD4 = smd 1.78 x 1.55: 1 -1.27,-3.5; 2 1.27,-3.5; 3 1.27,3.5; 4 -1.27,3.5
1X01' = drill 1.016 square: 1 0,0
D-PAK_TO252AA = smd 1 x 1.6: 1 -2.28,-4.8; 3 2.28,-4.8 | smd 5.4 x 6.2: 4 0,2.5
TO220AV = drill 1.016 long: B -2.54,-2.54; C 0,-2.54; E 2.54,-2.54
TO252 = smd 1 x 1.6: 1 -2.28,-4.8; 2 2.28,-4.8 | smd 5.4 x 6.2: 3 0,2.5
TO126AV = drill 1.016 long: B 2.286,-1.27; C 0,-1.27; E -2.286,-1.27
R2010 = smd 1.8 x 2.7: 1 -2.2,0; 2 2.2,0
CERAM55 = drill 1 pad 2.54 octagon: 1 -22.86,0; 2 22.86,0
0204/7 = drill 0.813 octagon: 1 -3.81,0; 2 3.81,0
CA6V = drill 1.016 long: A -2.54,-2.54; E 2.54,-2.54; S 0,2.54
RANDL = drill 0.9 long: A -4,5; E 4,5; S 0,5 | drill 1 square: P$1 -5,-5; P$2 5,-5
320NEW = drill 1.8 pad 3.81 octagon: 1 -4.928,7.823; 2 -4.928,0; 3 -4.928,-7.823; 4 4.928,7.823; 5 4.928,0; 6 4.928,-7.823
S64W = drill 0.7 long: A 2.54,1.27; E -2.54,1.27; S 0,1.27
SOT23-6 = smd 0.635 x 1.27: 1 -1.016,-1.016; 2 0,-1.016; 3 1.016,-1.016; 4 1.016,1.016; 5 0,1.016; 6 -1.016,1.016
TO3-K02 = drill 1.194 pad 3.81 octagon: 1 -1.778,-5.461; 2 -1.778,5.461 | drill 4.115 pad 6.477 round: 3 15.113,0; 3@ -15.113,0
0204V = drill 0.813 octagon: 1 -1.27,0; 2 1.27,0
C050-025X075 = drill 0.813 octagon: 1 -2.54,0; 2 2.54,0
R0402 = smd 0.7 x 0.9: 1 -0.65,0; 2 0.65,0
1X02 = drill 1.016 square: 1 -1.27,0 | drill 1.016 octagon: 2 1.27,0
0207/15 = drill 0.813 octagon: 1 -7.62,0; 2 7.62,0
0617/17 = drill 1.016 octagon: 1 -8.89,0; 2 8.89,0

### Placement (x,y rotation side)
A  9.84,34.61 270 top
A..C  10.79,41.27 180 top
C  8.89,33.97 270 top
C1  32.38,57.78 0 top
C2  33.24,88.84 90 top
C3  24.77,87.63 0 top
C4  36.83,15.88 0 top
C5  273.05,34.92 180 top
C6  101.6,86.36 0 top
C9  145.41,90.81 90 top
C10  104.78,93.98 270 top
C-1083  43.18,26.04 270 top
C-MABDT  25.72,49.53 90 top
C-MABDT1  37.72,82.87 270 top
C-SO1  24.13,60.96 180 top
C-SO8  31.11,35.56 180 top
C-TS  42.8,26.04 270 top
C.  8.57,33.97 270 top
CQ3  38.54,88.65 90 top
CR1  18.41,38.1 0 top
CR2  27.3,35.56 270 top
CR3  32.38,12.38 0 top
CR5  24.38,36.07 270 top
CTRIM3  13.92,15.24 90 top
D1  20.95,43.81 180 top
D2  37.91,91.25 0 top
D3  18.73,83.19 180 top
D4  12.7,24.13 270 top
D5  15.24,96.52 180 top
D6  34.29,93.34 0 top
D7  30.48,89.53 90 top
D8  98.42,15.24 180 top
D9  101.6,19.68 180 top
D10  74.93,15.24 0 top
D11  81.28,15.24 0 top
D12  137.79,20.32 90 top
D13  137.16,13.34 90 top
D14  113.03,15.24 0 top
D15  120.02,15.24 0 top
D16  272.42,18.41 180 top
D19  181.61,13.34 90 top
D20  181.61,20.32 90 top
D21  217.81,16.51 90 top
D22  217.17,23.5 90 top
D23  256.54,13.97 90 top
D24  253.37,20.95 90 top
D25  154.94,20.95 90 top
D26  150.5,13.97 90 top
D27  194.94,19.68 90 top
D28  190.5,14.61 90 top
D29  231.78,20.32 90 top
D30  229.24,13.97 90 top
DISP_R  125.09,97.79 0 top
DISP_R1  155.57,81.92 0 top
DISP_V  125.09,85.09 0 top
DISP_Z  124.46,94.61 0 top
DISP_Z1  159.38,80.01 270 top
DISP_Z2  161.93,80.01 270 top
F1  8.89,92.71 270 top
IC1  155.57,90.81 0 top
IC2  31.11,35.56 0 top
JP1  40.64,45.72 0 top
L1  97.16,93.98 90 top
L2  90.81,93.98 270 top
LED1  128.27,30.48 270 top
LED2  90.17,30.48 270 top
LED3  134.62,87.63 0 top
LED4  166.37,15.24 0 top
LED5  203.84,13.34 0 top
LED6  241.3,15.24 0 top
MINUS1  261.62,5.08 0 top
MINUS1X  255.27,5.08 0 top
MINUS2  223.52,5.08 0 top
MINUS2X  217.17,5.08 0 top
MINUS3  185.42,5.08 0 top
MINUS3X  179.07,5.08 0 top
MINUS4  147.32,5.08 0 top
MINUS4X  140.97,5.08 0 top
MINUS5  109.22,5.08 0 top
MINUS5X  102.87,5.08 0 top
MINUS60  256.62,97.08 0 top
MINUS120  218.62,97.08 0 top
OK1  76.2,27.94 0 top
OK2  74.3,95.25 90 top
OK3  114.3,27.94 0 top
OK4  153.03,45.72 0 top
OK5  191.77,42.55 0 top
OK6  226.69,44.45 0 top
OUT+  [1X01']  7.62,43.18 0 top
PLUS5  71.12,5.08 0 top
PLUS5X  76.2,5.08 0 top
PLUS120  237.62,97.08 0 top
PS_BOT  72.39,90.81 180 top
PS_EMIT  75.56,85.72 0 top
PS_TOP  67.31,90.81 180 top
PS_ZEN_FB  84.45,95.25 270 top
Q1  90.17,57.15 0 top
Q2  21.59,101.6 0 top
Q3  128.27,55.88 0 top
Q4  273.69,38.73 0 top
Q5  271.78,64.14 0 top
Q6  85.09,86.36 270 top
Q7  241.94,55.88 0 top
Q8  206.38,57.15 0 top
Q9  172.09,57.78 0 top
Q10  92.71,86.36 270 top
Q11  111.12,79.38 0 top
Q12  42.55,38.1 270 top
R1  42.04,89.92 90 top
R2  79.38,31.75 270 top
R3  99.69,31.75 270 top
R4  117.47,31.75 270 top
R5  134.62,31.75 270 top
R6  271.78,76.2 270 top
R7  270.51,55.24 180 top
R8  272.42,46.99 270 top
R9  272.42,42.55 180 top
R10  272.42,52.07 180 top
R11  272.42,20.95 0 top
R12  272.42,24.77 0 top
R13  155.57,31.75 270 top
R14  178.44,31.75 270 top
R15  193.68,31.75 270 top
R16  212.72,31.75 270 top
R17  231.78,31.75 270 top
R18  249.56,31.75 270 top
R19  147.96,81.28 270 top
R22  11.43,15.24 270 top
S1  186.06,97.79 0 top
T1  273.05,30.48 0 top
TO92S  24.13,60.96 0 top
TRIM1-  90.17,17.78 180 top
TRIM1-1  128.27,17.78 180 top
TRIM1-2  166.37,25.4 180 top
TRIM1-3  204.47,25.4 180 top
TRIM1-4  242.57,25.4 180 top
TRIM2-  90.17,13.97 0 top
TRIM2-1  128.27,13.97 0 top
TRIM2-2  166.37,21.59 0 top
TRIM2-3  204.47,21.59 0 top
TRIM2-4  242.57,21.59 0 top
U$1  111.12,85.72 0 top
U$2  151.76,90.81 180 top
V-1083  43.18,66.36 270 top
V-TO1  25.04,36.83 225 bottom
V-TO3  25.13,77.11 225 bottom
V-TS  43.18,66.36 270 top
V_C_IN(+)  6.35,25.4 270 top
V_OPTION  19.37,58.55 180 top
VC1  34.29,98.74 0 top
VC2  26.99,95.19 0 top
VC3  19.43,41.15 180 top
VC4  14.61,80.01 180 top
VCBRIDGE  28.39,53.98 90 top
VENT_RB  98.42,78.74 0 top
VENT_RT  92.71,78.74 0 top
VENTI  114.94,93.98 270 top
VIN(+)  21.59,93.98 270 top
VIN(-)  [1X01']  40.64,96.52 270 top
VIN(-)1  [1X01']  39.37,12.7 270 top
VIN+1  [1X01']  21.59,91.44 270 top
VOUT(+)  6.35,40.64 270 top
VOUT(+)1  237.49,104.14 0 top
VOUT(+)REG  40.64,50.8 270 top
VOUT-  40.64,55.88 180 top
VPOT1  11.43,62.55 270 top
VPOT2  15.24,62.55 270 top
VR1  21.59,69.53 180 top
VR2  32.38,78.42 180 top
VR3  28.26,88.96 270 top
VR4  12.06,73.03 0 top
VR5  21.59,66.04 180 top
VR6  20.32,62.23 90 top
VR7  28.26,88.9 270 top
VR8  32.83,76.83 180 top
VR9  20.32,96.52 0 top
VR10  46.35,83.82 90 top
VR11  91.44,26.04 0 top
VR12  127,44.45 90 top
VR13  76.2,19.05 0 top
VR14  82.55,28.57 90 top
VR16  67.94,95.25 270 top
VR17  132.72,80.01 0 top
VR18  137.79,95.89 0 top
VR19  138.43,80.01 0 top
VR22  77.47,90.81 0 top
VR23  80.64,95.25 90 top
VR25  170.18,45.72 90 top
VR26  205.1,43.81 90 top
VR27  239.4,43.81 90 top
VR28  114.3,19.05 0 top
VR29  120.65,41.91 90 top
VR30  159.38,44.45 90 top
VR31  197.49,43.81 90 top
VR32  233.04,45.72 90 top
VR33  187.32,26.04 90 top
VR34  225.43,31.11 90 top
VR35  150.5,29.21 90 top
VTRIM1  26.35,74.3 90 top
VTRIM2  24.77,15.24 90 top

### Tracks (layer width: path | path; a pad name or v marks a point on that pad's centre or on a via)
ADJ2  (via drill 0.6, 1)  (1 unrouted)
  Top 0.406: TO92S.1 22.23,62.23 C-SO1.4 22.23,63.65 VR6.2 v18.41,63.5 VPOT2.S VPOT1.S | 31.55,74.3 33.02,74.93 | V-1083.1 36.17,74.24 35.56,82.23 C-MABDT1.1 | V-TO3.2 19.68,74.3
  Top 1.27: v40.64,74.61 39.37,73.03 | 19.68,74.3 31.55,74.3 | v22.37,76.39 V-TO3.2
  Bottom 0.406: 39.91,72.3 V-1083.1 40.64,71.56 V-TS.1 | 39.91,72.3 39.37,72.83 | 39.91,72.3 40.64,73.03 v40.64,74.61 41.27,74.93 | v18.41,63.5 19.05,64.14
  Bottom 1.27: 19.05,64.14 arc30 22.23,73.66 v22.37,76.39
  pour Bottom (isolate 0.813, hatched): 39.37,76.83 43.18,76.83 43.18,69.22 41.91,67.94 39.37,67.94
  pour Top (isolate 0.813, hatched): 43.18,80.64 43.18,69.22 41.91,67.94 40.64,67.94 39.37,69.22 34.92,73.03 29.21,74.3 34.29,76.2 34.29,78.11 33.34,85.72
ADJUST  (via drill 0.6)
  Top 0.406: 27.53,37.21 CR2.1 | V-TO1.2 19.22,34.29 v17.02,34.29 17.14,33.66 | 29.21,36.83 C-SO8.4 | 29.21,36.83 29.21,36.2 IC2.1 | 9.62,31.68 8.98,31.68 C.A | D4.1 11.12,25.08 10.16,25.4 8.89,29.21 C.A | A.A C..A C.A | 29.21,36.83 28.57,36.83
  Top 1.016: 27.53,37.21 28.57,37.21 28.57,36.83
  Top 1.27: v29.21,28.26 26.67,28.51 arc-90 17.14,33.66 | CR1.1 16.76,36.01 v17.02,34.29 | C-MABDT.1 30.86,47.25 31.75,46.99 arc-49 35.24,36.58 arc71 38.1,31.75 39.5,31.75 C-1083.1
  Top 1.778: v38.73,40.64 36.2,40.64 35.56,40.01 35.56,36.89 35.24,36.58
  Bottom 0.406: C-TS.1 40.64,31.24 C-1083.1 39.5,32.38 | A.A 11.11,31.43 v17.02,34.29 | 29.84,33.02 IC2.1
  Bottom 1.27: 29.84,33.02 29.84,29.84 30.29,29.72 | v29.21,28.26 29.53,28.89 30.29,29.72 | 30.29,29.72 arc-37 37.47,31.75 39.37,31.75 C-1083.1
  Bottom 1.778: Q12.E 38.99,40.39 v38.73,40.64
  pour Bottom (isolate 0.813, hatched): 19.68,32.38 arc-90 17.78,30.48 7.62,30.48 arc-90 6.35,31.75 6.35,33.66 arc-90 7.62,34.92 10.79,34.92 arc-90 11.43,35.56 19.68,35.56
  pour Top (isolate 0.61): 29.84,39.37 23.5,39.37 23.5,37.47 28.57,36.2 28.57,35.56 29.84,35.56
B  (2 unrouted)
B1
  Bottom 0.406: 43.18,13.34 43.18,34.92 42.55,35.56 41.53,35.56 Q12.B
  Bottom 0.61: 43.18,13.34 arc-73 34.92,8.89 13.97,8.89 11.43,11.43 CTRIM3.S R22.S
B2  (2 unrouted)
B-Q1
  Top 0.406: 272.42,37.95 R8.2
  Top 0.61: 272.42,37.95 Q4.B 272.74,37.15 271.78,36.2 271.78,35.05 C5.2
BATT-  (via drill 0.6)  (4 unrouted)
  Top 0.406: VR16.2 67,92.88 66.84,92.88 66.04,92.08 66.04,90.94 PS_TOP.2 65.91,88.39 v66.04,88.27 | v84.45,91.44 PS_ZEN_FB.A | v113.67,80.01 Q11.2 | v102.23,78.74 VENT_RB.2 | v125.73,92.71 DISP_Z.A | C6.A 107.02,91.25 C10.- | R19.A 146.68,83.81 v148.59,84.45
  Top 0.61: IC1.8 U$2.2 | T1.2 273.84,29.22 R12.2 273.84,24.92 v274.95,27.3
  Bottom 0.406: v66.04,88.27 66.04,78.11 67.31,76.2 84.45,76.2 | 148.59,76.2 249.36,76.2 261.49,76.9 | 148.59,76.2 118.75,76.2 | 118.75,76.2 113.67,76.2 | 113.67,76.2 106.05,76.2 | 106.05,76.2 102.23,76.2 v102.23,78.74 100.33,80.64 90.81,80.64 90.17,80.01 90.17,77.47 88.9,76.2 84.45,76.2 | 84.45,76.2 v84.45,91.44 | 113.67,76.2 v113.67,80.01 | v125.73,92.71 121.28,92.71 118.75,89.53 118.75,76.2 | C10.- 106.05,89.53 106.05,76.2 | 148.59,76.2 v148.59,84.45 149.22,85.09 149.22,94.61 | 149.22,94.61 IC1.8 | C9.- 145.41,93.98 146.05,94.61 149.22,94.61
  Bottom 0.61: v274.95,27.3 270.51,27.3 268.61,25.4 268.61,11.43 265.43,8.26 264.8,8.26 MINUS1.1
  Bottom 2.54: S1.5 197.49,97.79 211.46,83.82 256.54,83.82 | 256.54,83.82 257.81,83.82 261.49,76.9 265.43,65.41 265.43,9.53 MINUS1.1 | MINUS60.1 256.62,83.9 256.54,83.82
D  (1 unrouted)
GATE
  Top 0.406: 270.51,52.55 270.51,58.42
  Top 0.61: Q4.C 273.69,42.39 R9.1 273.84,43.33 274.95,44.45 274.95,49.53 274.32,50.16 271.78,50.16 270.51,51.44 270.51,52.07 R10.2 270.51,52.55 | Q5.1 269.6,59.34 270.51,58.42
IN+1
  Top 0.406: 25.1,82.22 V-TO3.1 31.11,81.28 C-MABDT1.3 | TO92S.3 26.04,62.23 26.04,63.5 C-SO1.1
  Top 0.813: 26.04,59.05 26.04,63.5
  pour Bottom (isolate 0.813, hatched): 43.18,64.14 43.18,59.05 36.07,58.93 37.34,64.01
  pour Top (isolate 0.813, rank 3, hatched): 26.67,100.33 26.67,88.27 30.8,85.72 32.7,78.74 21.59,78.74 18.41,76.83 18.41,71.75 26.04,71.75 29.53,66.74 30.99,62.74 arc90 39.37,64.14 43.18,64.14 43.18,59.05 27.3,59.05 26.04,58.42 26.04,64.14 arc90 22.23,67.94 18.1,68.26 15.24,70.17 15.24,80.01 17.14,81.92 19.68,82.55 arc32 23.5,100.33
  pour Bottom (isolate 0.813, rank 4): 29.21,79.38 22.23,79.38 arc-20 23.5,100.33 26.67,100.33 26.67,87 27.94,85.72 31.75,85.72 31.75,80.64
IN-  (via drill 1.3)
  Top 2.54: v203.84,111.12 v40.64,111.12
  Bottom 0.406: 45.72,92.71 VR10.2 43.18,95.89 VIN(-).1
  Bottom 2.54: MINUS120.1 217.88,97.08 v203.84,111.12 | v40.64,111.12 VIN(-).1
  pour Bottom (isolate 0.813, rank 2): 43.18,99.69 47.62,90.81 35.56,90.81 35.56,99.69
  pour Top (isolate 0.813, hatched): 43.18,100.33 43.18,87.63 38.1,87.63 38.1,92.71 35.56,94.61 35.56,100.33
INPUT+  (via drill 0.6, 1)
  Top 0.406: C-SO8.1 32.7,40.96 v30.48,41.91 V-TO1.1 | C-TS.3 40.64,20.83 C-1083.3 | VC3.1 D1.C | 33.02,35.56 IC2.3 | C-SO8.1 33.02,38.73 | C-SO8.1 33.02,38.1 | C-MABDT.3 v30.48,49.78 VCBRIDGE.1
  Top 0.813: 33.02,38.1 33.02,35.56 33.02,33.66
  Bottom 0.406: 37.47,43.81 JP1.1 | C-1083.3 39.5,19.68 38.73,19.68 34.92,20.32 31.75,21.59 29.21,22.86 25.4,24.13 22.86,26.04 22.23,27.94 24.13,32.38 24.77,38.73 24.13,40.64 24.13,41.27 | v30.48,41.91 26.67,43.81 24.13,41.27 | 33.02,41.27 32.38,41.91 v30.48,41.91 | 24.13,41.27 VC3.1 | v30.48,41.91 v30.48,49.78
  pour Top (isolate 0.813, rank 2, hatched): 27.3,53.34 27.3,45.72 26.04,44.45 21.59,44.45 21.59,40.64 22.86,40.64 23.5,40.01 31.75,40.01 31.75,39.37 32.38,38.73 33.02,38.73 32.38,46.35 37.47,45.72 37.47,43.81 43.18,43.81 43.18,48.9 31.75,53.34
  pour Bottom (isolate 0.813, rank 2, hatched): 41.91,45.72 33.02,52.7 27.94,52.7 28.07,46.35 20.95,41.27 20.95,38.73 22.86,36.83 22.86,34.29 19.68,29.84 6.35,29.84 6.35,24.13 arc16 34.92,19.05 40.64,19.68 40.64,23.5 31.11,23.5 25.4,27.3 26.04,37.47 26.67,38.73 33.66,41.27
MINUS
  Top 0.406: D4.2 13.53,20.13 13.51,13.16 13.97,12.7 16.38,12.7 CTRIM3.A
  Bottom 0.406: R22.E 16.43,12.73 CTRIM3.A
N$1
  Bottom 0.406: VPOT2.A 16.43,60.01 VPOT1.E 17.27,58.55 V_OPTION.2
N$2
  Top 0.406: VR5.2 16.43,66.04 VPOT1.A 13.34,67.94 arc-135 13.34,71.75 VR4.2
  Bottom 0.813: VPOT2.E 17.78,66.47 VPOT1.A
N$3
  Top 0.406: VTRIM1.E VR8.2
  Bottom 0.813: VTRIM1.E 28.89,76.83
  pour Bottom (isolate 0.813, rank 2, hatched): 32.38,78.11 32.38,76.2 32.07,75.56 31.11,75.56 30.48,74.93 27.3,74.93 26.67,75.56 26.67,78.11
N$4
  Bottom 0.406: VR1.1 28.85,69.53 28.85,71.16
  Bottom 0.813: 28.85,71.16 VTRIM1.A
  pour Bottom (isolate 0.813, rank 3, hatched): 31.75,73.66 31.75,73.03 29.21,70.48 27.3,70.48 26.67,71.12 26.67,73.03 27.3,73.66
N$5
  Bottom 0.406: 17.73,18.41 CTRIM3.E 16.43,17.75 R22.A
  Bottom 0.61: VTRIM2.S 21,17.74 19.68,18.41 17.73,18.41
N$6
  Bottom 0.406: VTRIM2.A CR3.1
N$7
  Top 0.406: VR7.1 VR3.1
  Bottom 0.406: VR3.1 VC1.1 VC2.2
  pour Bottom (isolate 0.813, rank 3): 34.29,90.81 27.3,90.81 27.3,99.69 34.29,99.69
  pour Top (isolate 0.813, rank 4): 34.29,90.81 27.3,90.81 27.3,100.33 34.29,100.33
N$8  (8 unrouted)
N$9
  Bottom 1.27: VIN(-)1.1 C4.-
N$10  (2 unrouted)
N$11  (2 unrouted)
N$12  (2 unrouted)
  Top 0.406: VR3.2 VR7.2 29.88,87.83 D7.C
  Bottom 0.406: VR3.2 30.42,85.79 31.75,84.45 VR2.1 33.66,74.55 arc-57 23.56,63.63 20.64,61.78 V_OPTION.1
N$13
  Top 0.406: D6.C 31.75,92.08 D7.A
N$14  (via drill 0.6)  (1 unrouted)
  Top 0.406: D11.A v85.72,15.24
  Bottom 0.406: v85.72,15.24 TRIM2-.E
N$15  (2 unrouted)
N$16  (1 unrouted)
N$17  (1 unrouted)
N$18
  Top 0.61: T1.3 269.88,32.23 269.88,39.37 269.88,41.43 R9.2
N$19
  Top 0.61: D16.A 271.35,20.6 R11.1
N$20  (1 unrouted)
  Top 0.406: VR14.2 82.55,55.88 86.36,59.69 90.13,59.69 Q1.4
  Top 1.778: R3.1 99.69,56.52 96.52,59.69 90.21,59.69 Q1.4
N$21
  Top 0.61: R11.2 273.84,21.92 R12.1 270.99,28.27 T1.1
N$22
  Top 0.406: DISP_V.2 125.09,88.9 125.73,89.53 126.36,89.53 128.91,92.08 128.91,99.06 128.27,99.69 121.96,99.69 121.28,99.01
  Top 0.813: L1.2 97.16,98.42 97.79,99.06 113.67,99.06 | DISP_R.1 122.71,98.91 121.28,99.01 120.65,99.06 113.67,99.06 | 113.67,99.06 VENTI.1
  Bottom 0.406: VENTI.1 C10.+
N$23  (1 unrouted)
N$24
  Top 0.406: D8.C D9.A
N$25
  Top 0.406: VR11.2 96.04,28.73 96.52,41.91 88.27,50.16 88.27,51.98 Q1.1
N$26  (2 unrouted)
N$27  (2 unrouted)
N$28  (7 unrouted)
  Top 0.406: MINUS5X.1 102.87,6.35 106.05,9.53
  Top 1.778: 106.05,9.53 106.05,38.1 92.71,51.44 92.71,52.09 Q1.3
N$29  (1 unrouted)
N$30  (3 unrouted)
N$31  (2 unrouted)
N$32  (1 unrouted)
N$33  (1 unrouted)
N$34  (via drill 0.6)
  Top 0.406: LED3.2 131.42,90.78 128.91,88.27 v128.91,87.63
  Top 0.61: C9.+ 145.41,88.9 148.59,87 IC1.1 U$2.5 | v128.91,87.63 128.91,82.22 DISP_V.3
  Bottom 0.61: C9.+ 140.97,84.45 132.08,84.45 v128.91,87.63
N$35
  Top 0.61: U$2.1 153.42,91.82 154.31,92.71 IC1.7 154.31,95.25 155.57,99.69 162.56,99.69 169.54,95.25 169.54,78.11 167,74.93 135.89,74.93 134.14,78.59 VR17.2
N$36  (via drill 0.6)
  Top 0.61: v141.6,97.79 141.12,97.79 VR18.2 139.7,95.89 139.7,93.98 142.24,91.44 146.69,91.44 147.07,91.82 U$2.3
  Bottom 0.61: IC1.6 156.84,97.79 v141.6,97.79
N$37
  Top 0.61: IC1.5 160.66,94.61 167.64,93.34 167.64,79.38 165.74,76.2 140.49,76.2 VR19.2 140.34,80.49 140.34,87 143.51,90.17 147.32,90.17 147.7,89.79 U$2.4
N$38
  Top 0.813: Q10.3 84.86,84.05 83.82,85.09 83.82,85.24 Q6.E 77.28,85.41 PS_EMIT.2
N$39  (1 unrouted)
  Top 0.406: 89.07,89.11 88.04,89.94 89.53,91.44 90.84,91.44 | 89.07,89.11 Q10.1 | 90.84,91.44 91.44,91.44 | 90.84,91.44 L2.2 | Q6.B 84.14,87.31 86.36,89.53 88.64,89.53 89.07,89.11
N$40
  Top 0.406: Q6.C Q10.2 92.71,86.36 93.34,87 95.25,87 97.16,88.9 L1.1 99.39,90.84 C6.C
N$41
  Top 0.406: OK2.2 80.49,96.52 VR23.2 84.18,96.67 PS_ZEN_FB.C
N$42
  Top 0.406: VR22.2 78.89,91.29 78.74,91.44 78.74,92.08 78.11,92.71 78.11,93.67 OK2.1
N$43  (1 unrouted)
  Top 0.406: 72.39,99.06 88.9,99.06 L2.1 | 68.1,96.52 VR16.1 67.79,96.52 66.04,96.52 64.14,94.61 64.14,85.72 67.31,85.72 68.89,88.58 PS_TOP.1 PS_BOT.2
N$44  (via drill 0.6)  (4 unrouted)
  Top 0.406: VENT_RT.2 93.98,76.83 93.34,76.2 66.04,76.2 62.87,73.03 62.87,33.02 OK1.4 | OK3.4 110.8,31.44 109.86,32.38 109.86,72.39 108.58,73.66 v97.79,73.66 | v97.79,76.2 97.79,77.95 VENT_RB.1
  Bottom 0.406: v97.79,73.66 v97.79,76.2
N$45  (3 unrouted)
  Top 0.406: 110.17,75.56 110.17,75.25 109.86,74.93 66.04,74.93 64.14,73.03 64.14,34.92 66.04,33.66 76.83,33.66 76.83,32.08 OK1.3 | 110.17,75.56 Q11.1 | OK3.3 115.57,32.38 114.3,33.66 111.76,33.66 111.12,34.29 111.12,74.61 110.17,75.56
  Top 0.813: U$1.1 108.81,79 Q11.1
N$46
  Top 0.813: DISP_R.2 123.83,95.25 DISP_Z.C 122.12,89.33 121.28,88.27 121.28,82.22 DISP_V.1
N$47
  Top 0.813: VR17.1 131.29,83.15 LED3.1
N$48
  Top 0.61: VR18.1 136.37,91.03 LED3.3
N$49
  Top 0.813: VR19.1 137.01,84.09 LED3.4
N$50  (1 unrouted)
N$51  (1 unrouted)
N$52  (1 unrouted)
N$53
  Top 0.813: VENTI.2 111.12,88.9 U$1.2 Q11.3
N$54  (2 unrouted)
N$55  (2 unrouted)
N$56  (3 unrouted)
N$57  (2 unrouted)
N$58  (3 unrouted)
N$59  (8 unrouted)
N$60  (8 unrouted)
N$61  (3 unrouted)
N$62  (2 unrouted)
N$63  (2 unrouted)
N$64  (2 unrouted)
N$65  (2 unrouted)
N$66  (2 unrouted)
N$67  (2 unrouted)
N$68  (1 unrouted)
N$69
  Top 0.406: DISP_Z1.A 158.96,78.31 158.12,77.47 145.61,77.67 R19.E
N$70  (1 unrouted)
N$71  (1 unrouted)
N$72  (1 unrouted)
N$73  (1 unrouted)
N$74  (1 unrouted)
N$75
  Top 0.406: U$2.6 156.59,89.79 156.84,89.53 IC1.3 156.84,82.07 DISP_R1.2
N$76
  Top 0.406: DISP_R1.1 152.41,81.92 R19.S
N$77  (2 unrouted)
N$78  (2 unrouted)
N$79  (2 unrouted)
N$80  (1 unrouted)
N$81  (1 unrouted)
N$82  (1 unrouted)
N$83
  Top 0.406: DISP_Z1.C 159.38,81.28 161.93,78.74 DISP_Z2.A
OUT1  (via drill 0.6)
  Top 0.406: v32.38,15.88 33.02,23.44 V-TO1.3 | C-1083.2 35.83,26.04 V-TO1.3 | IC2.2 31.11,34.29 31.75,33.66 C-SO8.7 31.75,31.11 31.43,30.8 | 26.99,32.7 CR2.2 | 31.43,30.8 31.11,30.48 V-TO1.3 | C-MABDT.4 19.05,49.53 D1.A VC3.2 20.32,39.37 CR1.2 22.92,35.37 23.61,34.48 CR5.2 | 31.11,31.11 31.43,31.11 31.43,30.8
  Top 0.813: 30.48,31.11 31.11,31.11 31.11,38.1
  Bottom 0.406: 13.59,41.4 13.34,43.18 13.34,45.09 | A..C.A 13.59,41.4 | IC2.2 31.11,34.23 31.75,33.28 34.23,33.28 34.92,33.97 34.92,37.47 35.56,38.1 Q12.C | 13.59,41.4 VC3.2
  Bottom 1.27: v32.38,15.88 C4.+ CR3.2
  pour Top: 26.67,46.35 19.68,46.35 arc-90 17.78,44.45 arc-64 10.16,45.09 8.89,46.35 6.35,46.35 6.35,52.7 26.67,52.7
  pour Bottom (isolate 0.813, hatched): 41.91,26.67 40.64,26.67 38.1,29.21 38.1,29.84 37.47,30.48 33.02,30.48 36.2,33.02 36.83,33.66 36.83,36.2 38.73,38.1 39.37,38.1 39.37,38.73 36.83,39.37 34.92,39.37 30.54,39.05 26.42,37.78 26.16,26.1 arc33 36.83,22.23 37.47,22.23
  pour Top (isolate 0.813, rank 3, hatched): 10.79,45.09 19.05,45.09 20.32,43.81 20.32,39.37 17.78,39.37 17.78,36.83 20.95,38.73 22.86,37.47 25.4,34.29 31.11,34.29 38.1,27.3 38.1,20.95 34.92,19.05 34.92,11.43 29.84,18.41 29.84,19.05 21.59,23.5 13.34,26.67 10.79,29.21
  pour Bottom (rank 3): 26.67,46.35 19.68,40.01 15.88,36.2 11.43,36.2 11.43,41.91 9.53,45.72 5.71,45.72 5.71,52.7 26.67,52.7
OUT2  (via drill 0.6)
  Top 0.406: 24.13,59.05 24.07,59.05 C-SO1.7 | 24.13,65.41 23.01,65.41 VR5.1 | v39.37,81.92 C-MABDT1.4 | D3.A F1.1
  Top 0.813: 24.13,59.05 TO92S.2 24.13,65.41
  Bottom 0.406: 40.2,66.41 V-1083.2 V-TS.2 | 37.47,77.47 v39.37,81.92 | V-TO3.3 29.84,60.33 27.3,57.78 24.13,57.78 TO92S.2 | F1.1 8.89,93.34
  Bottom 1.27: 14.67,83.82 13.46,85.66 8.89,93.34 | V-1083.2 V-TO3.3 36.2,70.55 37.02,73.91 37.47,77.47
  other vias: 41.27,81.92 41.27,83.82 39.37,83.82
  pour Bottom (isolate 0.813, rank 6, hatched): 38.73,64.14 36.83,62.87 35.56,62.87 35.56,62.23 arc-68 15.88,54.61 arc-90 9.53,61.59 9.53,74.3 11.43,74.93 11.43,81.92 6.35,81.92 6.35,95.25 15.88,95.25 15.88,77.47 14.61,74.93 14.61,57.15 25.08,60.96 27.94,63.18 31.11,66.67 33.02,69.85 36.2,74.3 arc16 35.56,89.22 43.81,89.22 43.81,77.91 38.73,77.79
  pour Top (isolate 0.254, rank 2, hatched): 17.14,81.92 6.35,81.92 6.35,97.16 15.88,97.16 17.14,88.9
OUT+
  Top 0.406: A.C C..C C.C
  pour Bottom (isolate 0.813, rank 2, hatched): 10.79,36.2 5.71,36.2 5.71,46.35 8.89,45.72 10.79,43.81
PLUS5  (via drill 0.6, 1.3)  (8 unrouted)
  Top 0.406: LED2.A 83.34,22.38 81.28,19.68 81.28,10.79 R2.2 | D10.C 71.12,14.61 70.48,10.16 PLUS5.1 71.12,4.45 | OK2.4 72.39,93.98 73.97,92.39 PS_BOT.1 VR22.1 76.05,89.69 | 76.05,89.69 76.83,88.27 81.28,88.27 81.28,92.71 80.64,93.34 VR23.1 | 74.17,86.36 74.17,88.14 v74.3,88.27 76.05,89.69 | 74.17,86.36 PS_EMIT.1 | VENT_RT.1 76.2,78.74 74.3,81.28 74.17,86.36 | DISP_Z2.C 164.26,81.71 v164.47,81.92
  Top 0.61: D16.C 274.95,18.41 276.86,19.68 276.86,34.92 | R7.1 276.23,55.24 276.86,54.61 276.86,52.07 | 276.86,34.92 276.86,37.47 | 276.86,37.47 276.86,52.07 | 276.86,52.07 R10.1 | 276.86,34.92 C5.1 | Q4.E 276.69,37.63 276.86,37.47
  Top 2.54: v196.85,79.38 199.39,79.38 202.56,76.2 275.59,76.2 276.86,73.66 276.86,60.96
  Bottom 0.406: 74.3,102.23 v74.3,88.27 | v164.47,81.92 173.35,81.92 173.99,81.28
  Bottom 2.54: PLUS5.1 70.48,4.45 70.48,3.81 60.33,6.99 60.33,96.52 64.77,102.23 74.3,102.23 172.09,102.23 S1.2 179.07,98.42 173.99,93.34 173.99,81.28 176.53,79.38 v196.85,79.38
V+OUT  (via drill 0.6)  (2 unrouted)
  Top 0.61: R8.1 269.72,48.41 269.24,48.9 269.24,55.4 | 269.24,55.4 269.24,55.88 | 269.24,55.4 R7.2 267.33,55.24 266.7,55.88 266.7,71.12 v267.97,72.39
  Bottom 0.61: R6.1 271.14,80.01 | v267.97,72.39 267.97,79.38 268.61,80.01 271.93,80.01 272.22,80.3
  Bottom 2.54: R6.1 272.22,80.3 275.59,82.55 275.59,104.14 269.88,109.86 236.85,109.86 237.49,109.22 237.49,98.42 237.62,98.3 PLUS120.1
V-  (1 unrouted)
  Top 1.778: R1.1 45,87.72 46.35,87 VR10.1 46.35,59.05 43.81,56.52 VOUT-.1 36.2,56.52 C1.-
  Bottom 2.54: S1.4 190.98,109.37 189.23,111.12 53.34,111.12 51.44,109.22 51.44,66.67 43.81,56.52 VOUT-.1
VIN+  (via drill 1.3)
  Top 0.406: VR9.2 21.74,94.13 VIN(+).1
  Top 1.778: 22.23,106.68 21.59,102.23 Q2.C
  Top 2.54: v189.87,83.82 177.16,83.82 173.99,87 173.99,104.14 171.45,106.68 22.23,106.68
  Bottom 0.406: VIN+1.1 VIN(+).1 Q2.C
  Bottom 2.54: S1.6 190.98,84.94 v189.87,83.82
VIRT-  (3 unrouted)
  Top 0.406: D2.C 35.67,92.39 D6.A
VOUT+REG  (1 unrouted)
  Top 0.406: VR4.1 F1.2
  Bottom 2.54: S1.1 178.23,105.61 177.16,106.68 59.89,106.68 55.88,102.87 55.88,64.77 44.45,50.8
  pour Top (isolate 0.813, hatched): 43.18,49.53 39.37,49.53 arc25 33.02,53.98 31.11,54.61 12.7,54.61 arc-73 6.35,66.67 6.35,80.64 13.97,80.64 11.43,67.94 13.34,64.77 13.34,57.78 19.05,57.15 34.92,57.15 43.18,52.07

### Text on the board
Top: MICHAELS | 24112011
Bottom: 24112011 | MICHAELS
tNames: V_in(+) | V_out(+)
